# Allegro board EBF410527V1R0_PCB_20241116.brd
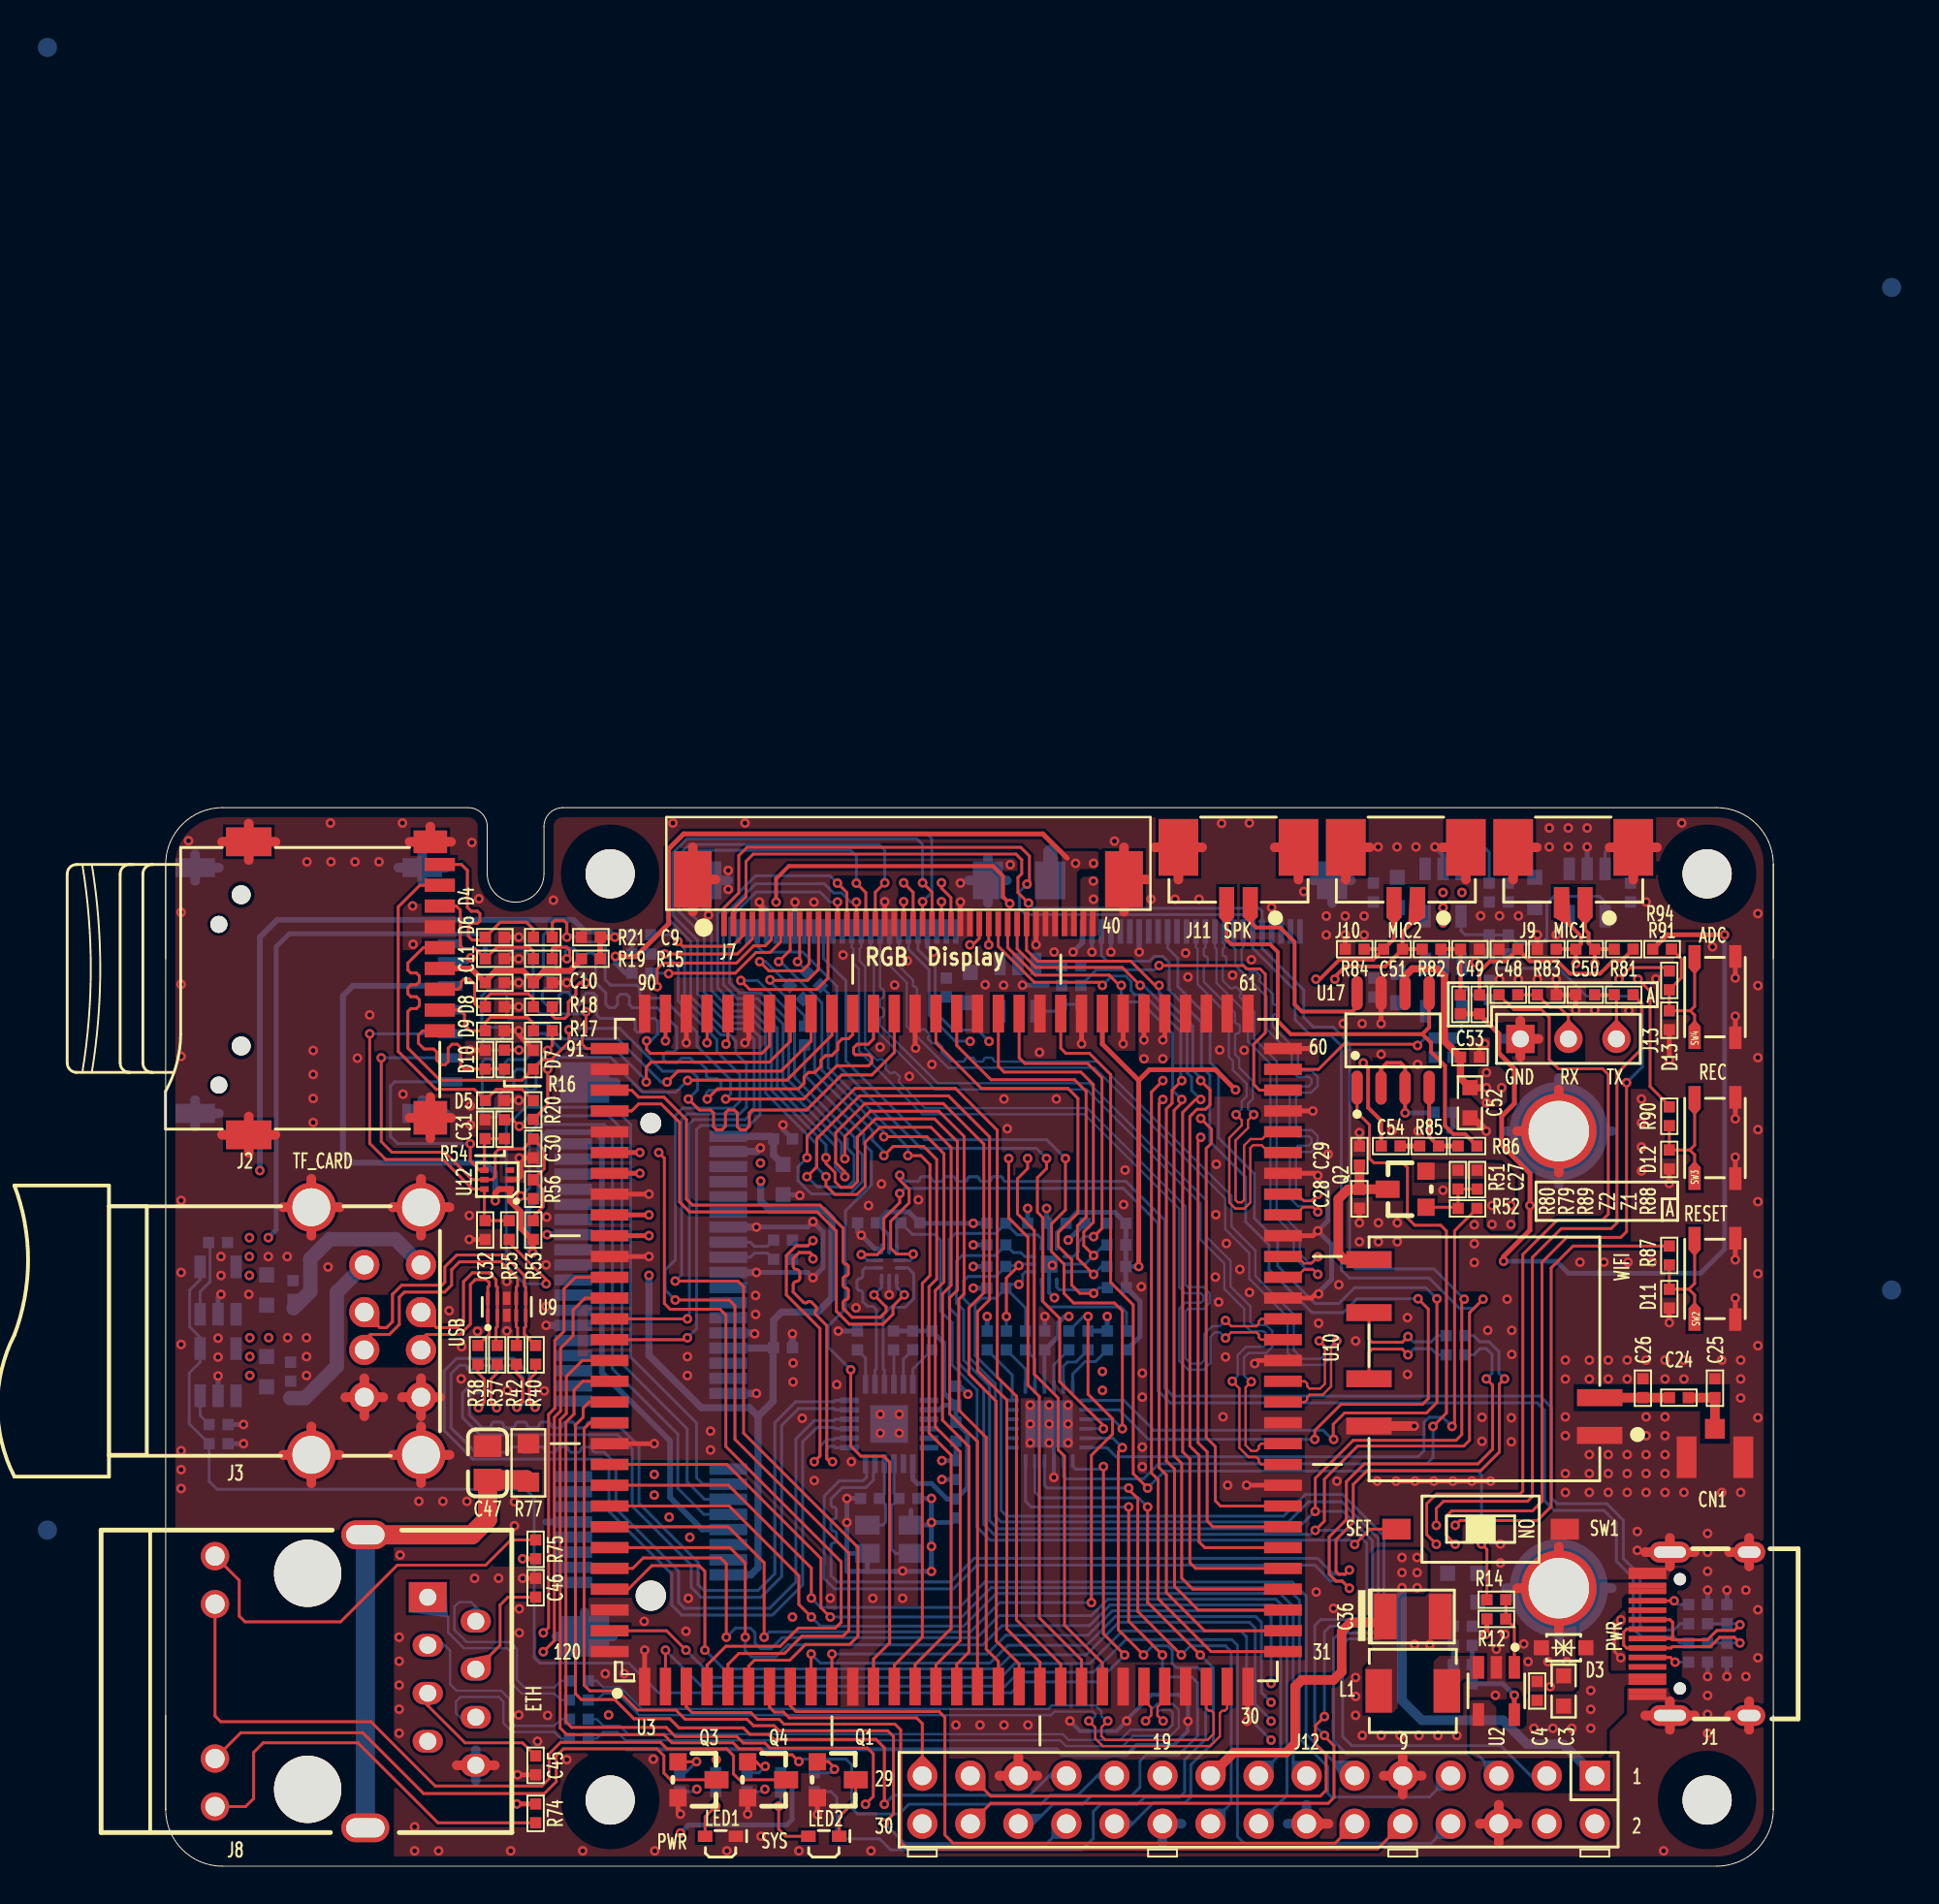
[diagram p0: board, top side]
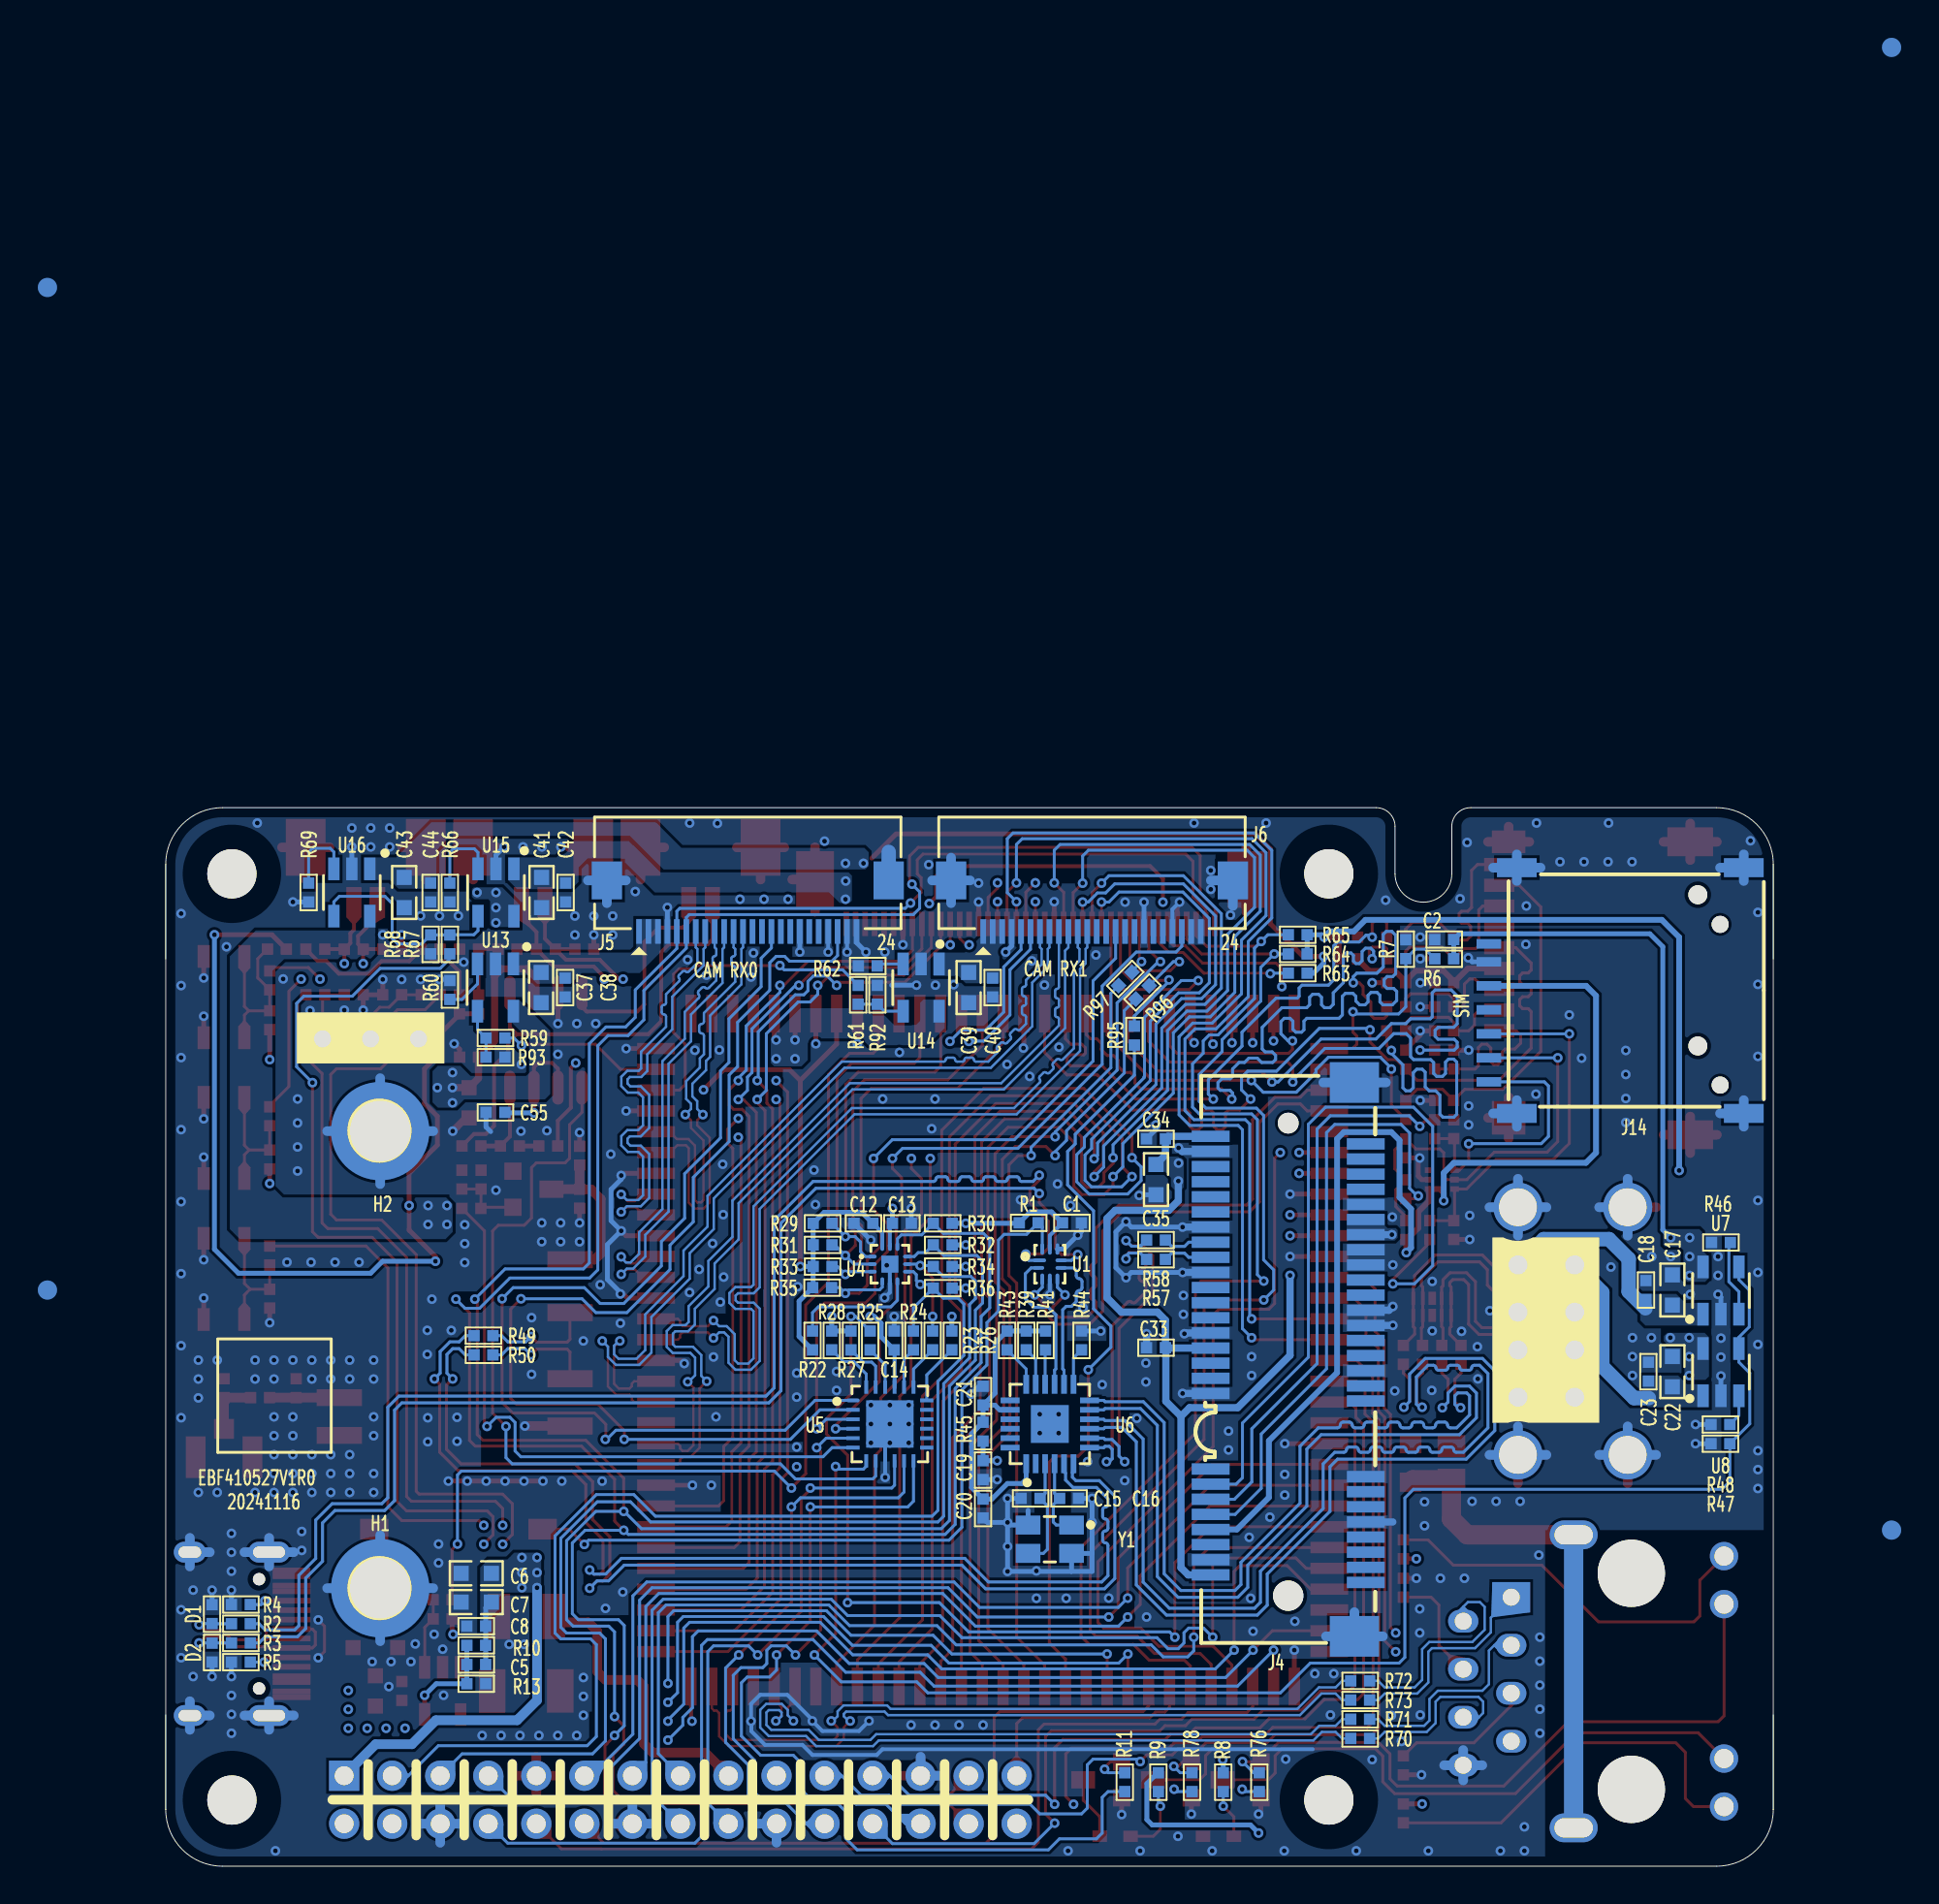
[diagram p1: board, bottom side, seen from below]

Outline 85 x 56 mm; copper layers: TOP, GND02, PWR03, BOTTOM. Coordinates in mm from the lower left corner of the outline.
Outline path: 0,53 0,3 ; 0,53 arc(0.88,55.12) 3,56 16,56 arc(16.71,55.71) 17,55 17,52.5 arc(17.44,51.44) 18.5,51 arc(19.56,51.44) 20,52.5 20,55 arc(20.29,55.71) 21,56 82,56 arc(84.12,55.12) 85,53 ; 0,53 0,48 ; 0,3 0,8 ; 0,3 arc(0.88,0.88) 3,0 82,0 arc(84.12,0.88) 85,3 ; 85,53 85,48 ; 85,53 85,3 ; 85,3 85,8

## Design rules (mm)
net group DBG_DN: nets DBG_DN N21432971
net group DBG_DP: nets DBG_DP N21432968
net group DM1: nets DM1 USB_DM1
net group DM2: nets DM2 USB_DM2
net group DP1: nets DP1 USB_DP1
net group DP2: nets DP2 USB_DP2
net group FEPHY_RXN: nets FEPHY_RXN N23717683
net group FEPHY_RXP: nets FEPHY_RXP N23717680
net group FEPHY_TXN: nets FEPHY_TXN N23717677
net group FEPHY_TXP: nets FEPHY_TXP N23717674
net group I2C3_SCL_LT: nets I2C3_SCL_LT N23825209
net group I2C3_SDA_LT: nets I2C3_SDA_LT N23825224
net group SDMMC_CMD: nets N23503652 SDMMC_CMD
net group SDMMC_D0: nets N23503668 SDMMC_D0
net group SDMMC_D1: nets N23503672 SDMMC_D1
net group SDMMC_D2: nets N23503644 SDMMC_D2
net group SDMMC_D3: nets N23503648 SDMMC_D3
net group SDMMC_DET: nets N23503676 SDMMC_DET
net group USB_4G_DM3: nets N23809847 USB_4G_DM3
net group USB_4G_DP3: nets N23809831 USB_4G_DP3
net group USB_DV: nets USB_RV_DM USB_RV_DP
net group USB_HUB: nets USB_HUB_DM USB_HUB_DP
net group USB_WLAN_DM4: nets N23719058 USB_WLAN_DM4
net group USB_WLAN_DP4: nets N23719056 USB_WLAN_DP4
net group XL9535_INT: nets N23825226 XL9535_INT
net group 50OHM: nets SIM_CLK0 SPI1_CLK_M0 VO_LCDC_CLK
net group PWR: nets HUB_3V3 SIM_VDD VCC3V3_SD VCC_1V8 VCC_WLAN

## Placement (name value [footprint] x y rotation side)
C1  0.1uF  [C0402]  37.08 34.04 180 bottom
C2  0.1uF  [C0402]  17.4 49.02 0 bottom
C3  10uF  [C0603]  73.91 9.27 90 top
C4  0.1uF  [C0402]  72.52 9.27 90 top
C5  22pF  [C0402]  68.58 10.67 0 bottom
C6  10uF  [C0603]  68.58 15.49 0 bottom
C7  10uF  [C0603]  68.58 13.97 0 bottom
C8  0.1uF  [C0402]  68.58 12.7 0 bottom
C9  0.1uF  [C0402]  22.48 49.15 180 top
C10  10uF  [C0402]  19.94 46.74 0 top
C11  0.1uF  [C0402]  17.4 46.74 0 top
C12  1uF  [C0402]  48.11 34.01 0 bottom
C13  1uF  [C0402]  46.08 34.01 180 bottom
C14  10uF  [C0402]  46.48 27.81 90 bottom
C15  NC  [C0402]  39.27 19.46 0 bottom
C16  NC  [C0402]  37.24 19.46 0 bottom
C17  10uF  [C0603]  5.33 30.48 90 bottom
C18  0.1uF  [C0402]  6.73 30.48 90 bottom
C19  0.1uF  [C0402]  41.78 20.95 270 bottom
C20  10uF  [C0402]  41.78 18.92 270 bottom
C21  0.1uF  [C0402]  41.78 24.89 90 bottom
C22  10uF  [C0603]  5.33 26.16 90 bottom
C23  0.1uF  [C0402]  6.6 26.16 90 bottom
C24  10pF  [C0402]  80.01 24.79 180 top
C25  NC  [C0402]  81.92 25.29 90 top
C26  NC  [C0402]  78.11 25.29 90 top
C27  0.1uF  [C0402]  69.34 36.32 270 top
C28  4.7uF  [C0402]  63.12 35.31 270 top
C29  0.1uF  [C0402]  63.12 37.59 90 top
C30  33pF  [C0402]  19.43 37.97 270 top
C31  33pF  [C0402]  16.89 38.99 90 top
C32  33pF  [C0402]  16.89 33.66 270 top
C33  0.1uF  [C0402]  32.64 27.43 0 bottom
C34  0.1uF  [C0402]  32.64 38.48 0 bottom
C35  10uF  [C0603]  32.64 36.32 270 bottom
C36  220uF  [CASE-B_3528]  65.94 13.21 0 top
C37  10uF  [C0603]  65.15 46.48 270 bottom
C38  0.1uF  [C0402]  63.88 46.48 270 bottom
C39  10uF  [C0603]  42.55 46.48 270 bottom
C40  0.1uF  [C0402]  41.27 46.48 270 bottom
C41  10uF  [C0603]  65.13 51.51 270 bottom
C42  0.1uF  [C0402]  63.86 51.51 270 bottom
C43  10uF  [C0603]  72.39 51.51 270 bottom
C44  0.1uF  [C0402]  70.99 51.51 270 bottom
C45  22nF  [C0402]  19.56 5.33 270 top
C46  22nF  [C0402]  19.56 14.73 90 top
C47  1nF  [C0805]  17.02 21.34 90 top
C48  NC  [C0402]  70.99 48.51 180 top
C49  NC  [C0402]  68.96 48.51 0 top
C50  NC  [C0402]  75.06 48.51 180 top
C51  NC  [C0402]  64.9 48.51 180 top
C52  10uF  [C0603]  68.96 40.39 270 top
C53  0.1uF  [C0402]  68.96 42.8 0 top
C54  0.22uF  [C0402]  64.77 38.1 0 top
C55  1uF  [C0402]  67.56 39.88 0 bottom
CN1  WiFi-Ant  [UFL-3]  81.92 21.64 180 top
D1  KLXES15AAA1  [ES0402]  82.55 13.34 270 bottom
D2  KLXES15AAA1  [ES0402]  82.55 11.3 90 bottom
D3  PESD5V0S1BA-N  [SOD323_CA]  73.91 11.56 180 top
D4  KLXES15AAA1  [ES0402]  17.4 49.15 0 top
D5  KLXES15AAA1  [ES0402]  17.4 40.51 0 top
D6  KLXES15AAA1  [ES0402]  17.4 48.01 0 top
D7  KLXES15AAA1  [ES0402]  19.43 42.67 90 top
D8  KLXES15AAA1  [ES0402]  17.4 45.47 0 top
D9  KLXES15AAA1  [ES0402]  17.4 44.2 0 top
D10  KLXES15AAA1  [ES0402]  16.89 42.67 90 top
D11  KLXES15AAA1  [ES0402]  79.5 30.02 90 top
D12  KLXES15AAA1  [ES0402]  79.5 37.39 90 top
D13  KLXES15AAA1  [ES0402]  79.5 44.75 90 top
H1  M2X3mm  [T3R2-5R2_TOPSMT]  73.66 14.71 180 bottom
H2  M2X3mm  [T3R2-5R2_TOPSMT]  73.66 38.89 180 bottom
J1  TYPE-C  [TYPE-C-31-M-12]  78.62 12.29 90 top
J2  TF_Card  [TFCARD]  3.99 47.39 270 top
J3  -  [USB-A-D]  7 28.31 90 top
J4  MINI-PCIE  [PCIE_52P]  25.65 26.81 90 bottom
J5  FPC_0P5_24P_D  [FPC_24P_0P5]  54.22 50.8 180 bottom
J6  FPC_0P5_24P_D  [FPC_24P_0P5]  36.02 50.8 180 bottom
J7  FPC_0R5_40P_D  [FPC-40P-0P5]  39.27 49.85 0 top
J8  HR911105A  [RJ45]  9.28 10.29 90 top
J9  -  [YTC-A1251-02AB]  74.42 51 0 top
J10  -  [YTC-A1251-02AB]  65.57 51 0 top
J11  -  [YTC-A1251-02AB]  56.72 51 0 top
J12  -  [HDR2X15-2R54-TM-VM]  57.78 3.52 180 top
J13  1X3PIN-M  [DIP_3P_2P54]  74.17 43.77 0 top
J14  SIM-7-1  [NANO_SIM]  8.3 46.32 90 bottom
L1  3.3uH  [L4520]  65.94 9.27 180 top
LED1  HS-0602-UR  [LED_HS_0602_UR]  29.34 1.58 180 top
LED2  HS-0602-UG  [LED_HS_0602_UR]  34.8 1.58 180 top
NOREF  -  []  -2 0 90 top
NOREF#2  -  []  79.25 24.89 0 top
NOREF#3  -  []  -10 1.52 0 top
NOREF#4  -  [unnamed#2]  -6.25 17.78 0 bottom
NOREF#5  -  [unnamed#2]  91.25 30.48 0 bottom
NOREF#6  -  [unnamed#2]  91.25 83.52 0 bottom
NOREF#7  -  [unnamed#2]  -6.25 96.22 0 bottom
Q1  SS8050  [SOT23]  35.45 4.57 270 top
Q2  SI2333  [SOT23]  65.65 35.81 90 top
Q3  SS8050  [SOT23]  28.08 4.57 270 top
Q4  SS8050  [SOT23]  31.76 4.57 270 top
R1  4.7K  [R0402]  39.37 34.04 180 bottom
R2  2.2R  [R0402]  81.03 12.83 180 bottom
R3  2.2R  [R0402]  81.03 11.81 180 bottom
R4  5.1K  [R0402]  81.03 13.84 0 bottom
R5  5.1K  [R0402]  81.03 10.79 0 bottom
R6  12K  [R0402]  17.4 48.01 0 bottom
R7  22K  [R0402]  19.43 48.51 90 bottom
R8  4.7K  [R0402]  29.08 4.45 270 bottom
R9  2.2K  [R0402]  32.51 4.45 270 bottom
R10  100K  [R0402]  68.58 11.68 0 bottom
R11  1K  [R0402]  34.29 4.45 90 bottom
R12  0R  [R0402]  70.36 13.08 0 top
R13  22K  [R0402]  68.58 9.65 180 bottom
R14  NC  [R0402]  70.36 14.1 0 top
R15  0R  [R0402]  22.48 48.01 180 top
R16  22R  [R0402]  17.91 42.67 270 top
R17  22R  [R0402]  19.94 44.2 180 top
R18  22R  [R0402]  19.94 45.47 180 top
R19  22R  [R0402]  19.94 48.01 180 top
R20  22R  [R0402]  19.43 40.01 90 top
R21  1K  [R0402]  19.94 49.15 180 top
R22  10K  [R0402]  50.8 27.81 90 bottom
R23  22R  [R0402]  44.45 27.81 270 bottom
R24  22R  [R0402]  45.47 27.81 270 bottom
R25  22R  [R0402]  47.75 27.81 270 bottom
R26  10K  [R0402]  43.43 27.81 270 bottom
R27  NC  [R0402]  48.77 27.81 270 bottom
R28  NC  [R0402]  49.78 27.81 270 bottom
R29  4.7K  [R0402]  50.27 34.01 180 bottom
R30  4.7K  [R0402]  43.92 34.01 0 bottom
R31  4.7K  [R0402]  50.27 32.87 180 bottom
R32  4.7K  [R0402]  43.92 32.87 0 bottom
R33  4.7K  [R0402]  50.27 31.72 180 bottom
R34  4.7K  [R0402]  43.92 31.72 0 bottom
R35  4.7K  [R0402]  50.29 30.61 180 bottom
R36  4.7K  [R0402]  43.92 30.58 0 bottom
R37  2.2R  [R0402]  17.53 27.05 270 top
R38  2.2R  [R0402]  16.51 27.05 270 top
R39  NC  [R0402]  39.5 27.81 270 bottom
R40  2.2R  [R0402]  19.56 27.05 270 top
R41  100K  [R0402]  38.48 27.81 270 bottom
R42  2.2R  [R0402]  18.54 27.05 270 top
R43  100K  [R0402]  40.51 27.81 270 bottom
R44  NC  [R0402]  36.58 27.81 90 bottom
R45  0R  [R0402]  41.78 22.99 90 bottom
R46  3.4K  [R0402]  2.77 32.99 0 bottom
R47  10K  [R0402]  2.79 22.35 0 bottom
R48  3.4K  [R0402]  2.79 23.37 0 bottom
R49  2.2R  [R0402]  68.2 28.07 180 bottom
R50  2.2R  [R0402]  68.2 27.05 180 bottom
R51  10K  [R0402]  68.33 36.32 270 top
R52  1K  [R0402]  68.83 34.8 180 top
R53  15K  [R0402]  19.43 33.66 90 top
R54  0R  [R0402]  17.91 38.99 270 top
R55  0R  [R0402]  18.16 33.66 90 top
R56  0R  [R0402]  19.43 35.81 90 top
R57  2.2R  [R0402]  32.64 32.11 0 bottom
R58  2.2R  [R0402]  32.64 33.12 0 bottom
R59  1K  [R0402]  67.56 43.81 0 bottom
R60  6.8K  [R0402]  69.98 46.35 90 bottom
R61  1K  [R0402]  48.39 46.1 270 bottom
R62  6.8K  [R0402]  47.88 47.62 0 bottom
R63  10K  [R0402]  25.15 47.24 0 bottom
R64  10K  [R0402]  25.15 48.26 0 bottom
R65  10K  [R0402]  25.15 49.28 0 bottom
R66  6.8K  [R0402]  69.98 51.51 270 bottom
R67  1K  [R0402]  69.98 48.77 90 bottom
R68  10K  [R0402]  70.99 48.77 270 bottom
R69  6.8K  [R0402]  77.44 51.51 270 bottom
R70  0R  [R0402]  21.84 6.76 180 bottom
R71  0R  [R0402]  21.84 7.77 180 bottom
R72  0R  [R0402]  21.84 9.8 180 bottom
R73  0R  [R0402]  21.84 8.79 180 bottom
R74  1K  [R0402]  19.56 2.79 270 top
R75  1K  [R0402]  19.56 16.76 90 top
R76  1K  [R0402]  27.18 4.45 90 bottom
R77  1M  [R0805]  19.18 21.34 90 top
R78  1K  [R0402]  30.73 4.45 90 bottom
R79  NC  [R0402]  69.47 45.59 90 top
R80  NC  [R0402]  68.45 45.59 90 top
R81  NC  [R0402]  77.09 48.51 0 top
R82  NC  [R0402]  66.93 48.51 0 top
R83  NC  [R0402]  73.03 48.51 180 top
R84  NC  [R0402]  62.87 48.51 180 top
R85  20K  [R0402]  66.8 38.1 0 top
R86  100K  [R0402]  68.83 38.1 0 top
R87  100R  [R0402]  79.5 32.31 270 top
R88  510R  [R0402]  77.09 46.1 0 top
R89  510R  [R0402]  70.99 46.1 180 top
R90  100R  [R0402]  79.5 39.67 270 top
R91  100R  [R0402]  79.5 46.86 270 top
R92  10K  [R0402]  47.37 46.1 90 bottom
R93  10K  [R0402]  67.56 42.8 180 bottom
R94  10K  [R0402]  79.12 48.51 180 top
R95  40.2R  [R0402]  33.78 43.94 90 bottom
R96  40.2R  [R0402]  33.35 46.23 135 bottom
R97  40.2R  [R0402]  34.26 46.94 135 bottom
SS1  NPTH_M2.5  [NPTH_M2R5]  23.5 3.5 0 top
SS2  NPTH_M2.5  [NPTH_M2R5]  81.5 3.5 0 top
SS3  NPTH_M2.5  [NPTH_M2R5]  81.5 52.5 0 top
SS4  NPTH_M2.5  [NPTH_M2R5]  23.5 52.5 0 top
SW1  DSIC01LS-P  [SW2-6R20X3R50-SM]  69.52 17.83 0 top
SW2  SW_PB_ESW  [SW4-4R20X3R25-SM]  81.92 31.07 270 top
SW3  SW_PB_ESW  [SW4-4R20X3R25-SM]  81.92 38.52 270 top
SW4  SW_PB_ESW  [SW4-4R20X3R25-SM]  81.92 45.98 270 top
U1  TS3USB30ERSWR  [UQFN_10]  38.25 31.85 180 bottom
U2  RY3430  [SOT23-5]  70.36 9.27 180 top
U3  -  [RV1106-35X35-HOLE-B-120P]  41.27 27.3 0 top
U4  RS0104YTQE12  [QFN12L-0R4-2X2EP1R20X1R00]  46.71 31.85 180 bottom
U5  XL9535QF24  [QFN24-4X4EP2R70X2R70]  46.71 23.39 180 bottom
U6  CH334F  [QFN24]  38.25 23.39 90 bottom
U7  LPW5209AB5F  [SOT23-5]  2.77 30.45 180 bottom
U8  LPW5209AB5F  [SOT23-5]  2.77 26.14 180 bottom
U9  RCLAMP0524P  [USON_10]  18.03 29.59 0 top
U10  TL8800DLUA  [SMD6-12R9X12R2]  69.72 26.84 90 top
U12  NUP5120X6T1G  [SOT563]  17.53 36.32 90 top
U13  LPW5209AB5F  [SOT23-5]  67.56 46.48 0 bottom
U14  LPW5209AB5F  [SOT23-5]  45.06 46.48 0 bottom
U15  LPW5209AB5F  [SOT23-5]  67.54 51.51 0 bottom
U16  LPW5209AB5F  [SOT23-5]  75.16 51.51 0 bottom
U17  8002A  [SOP8]  64.9 43.69 0 top
Y1  12MHz  [3225]  38.25 17.3 0 bottom
Z1  KLXES15AAA1  [ES0402]  75.06 46.1 180 top
Z2  KLXES15AAA1  [ES0402]  73.03 46.1 0 top

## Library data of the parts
C1-C35 C37-C55 = CAP_NP
C36 = CAP
CN1 = WIFI_ANT
D1-D13 Z1 Z2 = DIODE BI-DIR TRIG
H1 H2 SS1-SS4 = SPACER
J1 = TYPE-C-31-M-12
J2 = TF_Card
J3 = USB-A-D
J4 = MINI-PCIE
J5 J6 = FPC-24P
J7 = FPC-40P
J8 = RJ45_HR961160C
J9-J11 = 1X2PIN_SH
J12 = 2X15PIN
J13 = 1X3PIN
J14 = SIM-7-1
L1 = IND
LED1 LED2 = LED
Q1 Q3 Q4 = NPN
Q2 = MOSFET_P
R1 R4-R15 R22 R26-R36 R39 R41 R43-R48 R51-R56 R59-R69 R74-R97 = RES
R2 R3 R37 R38 R40 R42 R49 R50 R57 R58 = RES: signal model: RES_R0402_DISCRETE_2.2R_2.2R
R16-R20 R23-R25 = RES: signal model: RES_R0402_DISCRETE_22R_22R
R21 = RES: signal model: RES_R0402_DISCRETE_1K_1K
R70-R73 = RES: signal model: RES_R0402_DISCRETE_0R_0R
SW1 = SW01
SW2-SW4 = SW_PB_ESW
U1 = TS3USB30ERSWR
U2 = MT3520B
U3 = RV1106G_CORE_120P
U4 = RS0104YTQE12
U5 = XL9535QF24
U6 = CH334F
U7 U8 U13-U16 = LPW5209AB5F
U9 = RCLAMP0524P
U10 = TL8800DLUA
U12 = NUP5120-D
U17 = 8002A
Y1 = CRYSTAL_4P

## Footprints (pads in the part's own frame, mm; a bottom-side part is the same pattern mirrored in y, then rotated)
3225
  rect 1.3x1 smd: 1(-1.15,-0.75) 2(1.15,-0.75) 3(1.15,0.75) 4(-1.15,0.75)
C0402
  rect 0.599x0.599 smd: 1(-0.5,0) 2(0.5,0)
C0603
  rect 0.8x0.8 smd: 1(-0.8,0) 2(0.8,0)
C0805
  rect 1.16x1.47 smd: 1(-0.89,0) 2(0.89,0)
CASE-B_3528
  rect 1.2x2.4 smd: 1(-1.45,0) 2(1.45,0)
DIP_3P_2P54
  rect 1.5x1.5 hole 0.9: 1(-2.54,0)
  round 1.5 hole 0.9: 2(0,0) 3(2.54,0)
ES0402
  rect 0.599x0.599 smd: 1(-0.5,0) 2(0.5,0)
FPC-40P-0P5
  rect 0.3x1.3 smd: 1(-9.75,0) 2(-9.25,0) 3(-8.75,0) 4(-8.25,0) 5(-7.75,0) 6(-7.25,0) 7(-6.75,0) 8(-6.25,0) 9(-5.75,0) 10(-5.25,0) 11(-4.75,0) 12(-4.25,0) 13(-3.75,0) 14(-3.25,0) 15(-2.75,0) 16(-2.25,0) 17(-1.75,0) 18(-1.25,0) 19(-0.75,0) 20(-0.25,0) 21(0.25,0) 22(0.75,0) 23(1.25,0) 24(1.75,0) 25(2.25,0) 26(2.75,0) 27(3.25,0) 28(3.75,0) 29(4.25,0) 30(4.75,0) 31(5.25,0) 32(5.75,0) 33(6.25,0) 34(6.75,0) 35(7.25,0) 36(7.75,0) 37(8.25,0) 38(8.75,0) 39(9.25,0) 40(9.75,0)
  rect 2x3 smd: 41(11.4,2.35) 42(-11.4,2.35)
FPC_24P_0P5
  rect 0.3x1.3 smd: 1(-5.75,-1.351) 2(-5.25,-1.351) 3(-4.75,-1.351) 4(-4.25,-1.351) 5(-3.75,-1.351) 6(-3.25,-1.351) 7(-2.75,-1.351) 8(-2.25,-1.351) 9(-1.75,-1.351) 10(-1.25,-1.351) 11(-0.75,-1.351) 12(-0.25,-1.351) 13(0.25,-1.351) 14(0.75,-1.351) 15(1.25,-1.351) 16(1.75,-1.351) 17(2.25,-1.351) 18(2.75,-1.351) 19(3.25,-1.351) 20(3.75,-1.351) 21(4.25,-1.351) 22(4.75,-1.351) 23(5.25,-1.351) 24(5.75,-1.351)
  rect 1.6x2 smd: 25(7.45,1.351) 26(-7.45,1.351)
HDR2X15-2R54-TM-VM
  rect 1.6x1.6 hole 1: 1(-17.78,-1.27)
  round 1.6 hole 1: 2(-17.78,1.27) 3(-15.24,-1.27) 4(-15.24,1.27) 5(-12.7,-1.27) 6(-12.7,1.27) 7(-10.16,-1.27) 8(-10.16,1.27) 9(-7.62,-1.27) 10(-7.62,1.27) 11(-5.08,-1.27) 12(-5.08,1.27) 13(-2.54,-1.27) 14(-2.54,1.27) 15(0,-1.27) 16(0,1.27) 17(2.54,-1.27) 18(2.54,1.27) 19(5.08,-1.27) 20(5.08,1.27) 21(7.62,-1.27) 22(7.62,1.27) 23(10.16,-1.27) 24(10.16,1.27) 25(12.7,-1.27) 26(12.7,1.27) 27(15.24,-1.27) 28(15.24,1.27) 29(17.78,-1.27) 30(17.78,1.27)
L4520
  rect 1.4x2.3 smd: 1(-1.8,0) 2(1.8,0)
LED_HS_0602_UR
  rect 0.77x0.599 smd: 1(-0.815,0) 2(0.815,0)
NANO_SIM
  round 0.9 hole 0.9 unplated: (-5,-5.49) (3.5,-5.49)
  rect 0.5x1.3 smd: 1(0.25,6.74) 2(-2.29,6.74) 3(-4.83,6.74) 4(2.47,6.74) 5(1.52,6.74) 6(-1.02,6.74) 7(-3.56,6.74)
  rect 1x2.1 smd: 8(-6.5,5.26) 9(6.5,5.26) 10(-6.5,-6.74) 11(6.5,-6.74)
NPTH_M2R5
  round 2.6 hole 2.6 unplated: (0,0)
PCIE_52P
  round 1.6 hole 1.6 unplated: (-12.5,0)
  round 1.1 hole 1.1 unplated: (12.5,0)
  rect 0.6x2 smd: 1(-11.8,-4.1) 2(-11.4,4.1) 3(-11,-4.1) 4(-10.6,4.1) 5(-10.2,-4.1) 6(-9.8,4.1) 7(-9.4,-4.1) 8(-9,4.1) 9(-8.6,-4.1) 10(-8.2,4.1) 11(-7.8,-4.1) 12(-7.4,4.1) 13(-7,-4.1) 14(-6.6,4.1) 15(-6.2,-4.1) 16(-5.8,4.1) 17(-2.2,-4.1) 18(-1.8,4.1) 19(-1.4,-4.1) 20(-1,4.1) 21(-0.6,-4.1) 22(-0.2,4.1) 23(0.2,-4.1) 24(0.6,4.1) 25(1,-4.1) 26(1.4,4.1) 27(1.8,-4.1) 28(2.2,4.1) 29(2.6,-4.1) 30(3,4.1) 31(3.4,-4.1) 32(3.8,4.1) 33(4.2,-4.1) 34(4.6,4.1) 35(5,-4.1) 36(5.4,4.1) 37(5.8,-4.1) 38(6.2,4.1) 39(6.6,-4.1) 40(7,4.1) 41(7.4,-4.1) 42(7.8,4.1) 43(8.2,-4.1) 44(8.6,4.1) 45(9,-4.1) 46(9.4,4.1) 47(9.8,-4.1) 48(10.2,4.1) 49(10.6,-4.1) 50(11,4.1) 51(11.4,-4.1) 52(11.8,4.1)
  rect 2.15x2.6 smd: 53(14.65,-3.5) 54(-14.65,-3.5)
QFN12L-0R4-2X2EP1R20X1R00
  oval 0.45x0.2 smd: 1(-0.925,0.4) 2(-0.925,0) 3(-0.925,-0.4) 7(0.925,-0.4) 8(0.925,0) 9(0.925,0.4)
  oval 0.2x0.45 smd: 4(-0.4,-0.925) 5(0,-0.925) 6(0.4,-0.925) 10(0.4,0.925) 11(0,0.925) 12(-0.4,0.925)
  rect 0.9x0.9 smd: 13(0,0)
QFN24
  rect 1x0.3 smd: 1(-2.1,1.25) 2(-2.1,0.75) 3(-2.1,0.25) 4(-2.1,-0.25) 5(-2.1,-0.75) 6(-2.1,-1.25) 13(2.1,-1.25) 14(2.1,-0.75) 15(2.1,-0.25) 16(2.1,0.25) 17(2.1,0.75) 18(2.1,1.25)
  rect 0.3x1 smd: 7(-1.25,-2.1) 8(-0.75,-2.1) 9(-0.25,-2.1) 10(0.25,-2.1) 11(0.75,-2.1) 12(1.25,-2.1) 19(1.25,2.1) 20(0.75,2.1) 21(0.25,2.1) 22(-0.25,2.1) 23(-0.75,2.1) 24(-1.25,2.1)
  rect 2x2 smd: 25(0,0)
QFN24-4X4EP2R70X2R70
  oval 0.7x0.2 smd: 1(-1.95,1.25)
  rect 0.7x0.2 smd: 2(-1.95,0.75) 3(-1.95,0.25) 4(-1.95,-0.25) 5(-1.95,-0.75) 6(-1.95,-1.25) 13(1.95,-1.25) 14(1.95,-0.75) 15(1.95,-0.25) 16(1.95,0.25) 17(1.95,0.75) 18(1.95,1.25)
  rect 0.2x0.7 smd: 7(-1.25,-1.95) 8(-0.75,-1.95) 9(-0.25,-1.95) 10(0.25,-1.95) 11(0.75,-1.95) 12(1.25,-1.95) 19(1.25,1.95) 20(0.75,1.95) 21(0.25,1.95) 22(-0.25,1.95) 23(-0.75,1.95) 24(-1.25,1.95)
  rect 2.5x2.5 smd: 25(0,0)
R0402
  rect 0.599x0.599 smd: 1(-0.5,0) 2(0.5,0)
R0805
  rect 1.016x1.143 smd: 1(-1.016,0) 2(1.016,0)
RJ45
  round 3.556 hole 3.556 unplated: (-6.223,1.778) (5.207,1.778)
  rect 1.6x2 hole 0.9: 1(3.942,-4.572)
  oval 1.2x1.6 hole 0.9: 2(2.672,-7.112) 3(1.402,-4.572) 4(0.132,-7.112) 5(-1.138,-4.572) 6(-2.408,-7.112) 7(-3.678,-4.572) 8(-4.948,-7.112)
  round 1.5 hole 1.02: 9(6.117,6.678) 10(3.577,6.678) 11(-4.593,6.678) 12(-7.133,6.678)
  oval 1.524x2.54 hole 1.016x2.032: 13(7.242,-1.272) 14(-8.258,-1.272)
RV1106-35X35-HOLE-B-120P
  rect 0.6x2 smd: 1(-15.95,-17.8) 2(-14.85,-17.8) 3(-13.75,-17.8) 4(-12.65,-17.8) 5(-11.55,-17.8) 6(-10.45,-17.8) 7(-9.35,-17.8) 8(-8.25,-17.8) 9(-7.15,-17.8) 10(-6.05,-17.8) 11(-4.95,-17.8) 12(-3.85,-17.8) 13(-2.75,-17.8) 14(-1.65,-17.8) 15(-0.55,-17.8) 16(0.55,-17.8) 17(1.65,-17.8) 18(2.75,-17.8) 19(3.85,-17.8) 20(4.95,-17.8) 21(6.05,-17.8) 22(7.15,-17.8) 23(8.25,-17.8) 24(9.35,-17.8) 25(10.45,-17.8) 26(11.55,-17.8) 27(12.65,-17.8) 28(13.75,-17.8) 29(14.85,-17.8) 30(15.95,-17.8) 61(15.95,17.8) 62(14.85,17.8) 63(13.75,17.8) 64(12.65,17.8) 65(11.55,17.8) 66(10.45,17.8) 67(9.35,17.8) 68(8.25,17.8) 69(7.15,17.8) 70(6.05,17.8) 71(4.95,17.8) 72(3.85,17.8) 73(2.75,17.8) 74(1.65,17.8) 75(0.55,17.8) 76(-0.55,17.8) 77(-1.65,17.8) 78(-2.75,17.8) 79(-3.85,17.8) 80(-4.95,17.8) 81(-6.05,17.8) 82(-7.15,17.8) 83(-8.25,17.8) 84(-9.35,17.8) 85(-10.45,17.8) 86(-11.55,17.8) 87(-12.65,17.8) 88(-13.75,17.8) 89(-14.85,17.8) 90(-15.95,17.8)
  rect 2x0.6 smd: 31(17.8,-15.95) 32(17.8,-14.85) 33(17.8,-13.75) 34(17.8,-12.65) 35(17.8,-11.55) 36(17.8,-10.45) 37(17.8,-9.35) 38(17.8,-8.25) 39(17.8,-7.15) 40(17.8,-6.05) 41(17.8,-4.95) 42(17.8,-3.85) 43(17.8,-2.75) 44(17.8,-1.65) 45(17.8,-0.55) 46(17.8,0.55) 47(17.8,1.65) 48(17.8,2.75) 49(17.8,3.85) 50(17.8,4.95) 51(17.8,6.05) 52(17.8,7.15) 53(17.8,8.25) 54(17.8,9.35) 55(17.8,10.45) 56(17.8,11.55) 57(17.8,12.65) 58(17.8,13.75) 59(17.8,14.85) 60(17.8,15.95) 91(-17.8,15.95) 92(-17.8,14.85) 93(-17.8,13.75) 94(-17.8,12.65) 95(-17.8,11.55) 96(-17.8,10.45) 97(-17.8,9.35) 98(-17.8,8.25) 99(-17.8,7.15) 100(-17.8,6.05) 101(-17.8,4.95) 102(-17.8,3.85) 103(-17.8,2.75) 104(-17.8,1.65) 105(-17.8,0.55) 106(-17.8,-0.55) 107(-17.8,-1.65) 108(-17.8,-2.75) 109(-17.8,-3.85) 110(-17.8,-4.95) 111(-17.8,-6.05) 112(-17.8,-7.15) 113(-17.8,-8.25) 114(-17.8,-9.35) 115(-17.8,-10.45) 116(-17.8,-11.55) 117(-17.8,-12.65) 118(-17.8,-13.75) 119(-17.8,-14.85) 120(-17.8,-15.95)
SMD6-12R9X12R2
  rect 0.9x2.4 smd: 1(-4.05,-6.1) 2(-2.05,-6.1) 3(-3.55,6.1) 4(-1.05,6.1) 5(2.45,6.1) 6(5.25,6.1)
SOD323_CA
  rect 0.8x0.8 smd: 1(-1.175,0) 2(1.175,0)
SOP8
  oval 0.6x1.8 smd: 1(-1.905,-2.5) 2(-0.635,-2.5) 3(0.635,-2.5) 4(1.905,-2.5) 5(1.905,2.5) 6(0.635,2.5) 7(-0.635,2.5) 8(-1.905,2.5)
SOT23
  rect 0.914x0.914 smd: 1(-0.953,-0.991) 2(0.953,-0.991)
  rect 0.914x1.27 smd: 3(0,1.041)
SOT23-5
  rect 0.599x1.199 smd: 1(-0.95,-1.25) 2(0,-1.25) 3(0.95,-1.25) 4(0.95,1.25) 5(-0.95,1.25)
SOT563
  rect 0.3x0.45 smd: 1(-0.5,-0.675) 2(0,-0.675) 3(0.5,-0.675) 4(0.5,0.675) 5(0,0.675) 6(-0.5,0.675)
SW2-6R20X3R50-SM
  rect 1.5x1.1 smd: 1(-4.45,0) 2(4.45,0)
SW4-4R20X3R25-SM
  rect 1.2x0.65 smd: 1(-2.15,1.075) 2(2.15,1.075) 3(2.15,-1.075) 4(-2.15,-1.075)
T3R2-5R2_TOPSMT
  round 4 hole 3.2: 1(0,0)
TFCARD
  round 1 hole 1 unplated: (-4,0) (4,0)
  rect 0.7x1.6 smd: 1(3.2,10.5) 2(2.1,10.5) 3(1,10.5) 4(-0.1,10.5) 5(-1.2,10.5) 6(-2.3,10.5) 7(-3.4,10.5) 8(-4.5,10.5) 9(-5.6,10.5)
  rect 1.2x1.778 smd: 10(-6.8,10)
  rect 1.524x2.413 smd: 11(-6.8,0.4) 12(8.7,0.4)
  rect 1.778x1.778 smd: 13(7.8,10)
TYPE-C-31-M-12
  round 0.65 hole 0.65 unplated: (-2.891,-1.44) (2.891,-1.44)
  rect 0.3x2 smd: A1(-3.35,0.279) A4(-2.55,0.279) A5(-1.25,0.279) A6(-0.249,0.279) A7(0.249,0.279) A8(1.25,0.279) A9(2.55,0.279) A12(3.35,0.279) B1(3.051,0.279) B4(2.25,0.279) B5(1.75,0.279) B6(0.749,0.279) B7(-0.749,0.279) B8(-1.75,0.279) B9(-2.25,0.279) B12(-3.051,0.279)
  oval 1.1x1.699 hole 0.599x1.199: C1(-4.321,-5.1) C2(4.321,-5.1)
  oval 1.1x2.2 hole 0.599x1.699: C3(-4.321,-0.909) C4(4.321,-0.909)
UFL-3
  rect 1.05x1.05 smd: 1(0,-1.5)
  rect 1.05x2.2 smd: 2(-1.5,0) 3(1.5,0)
unnamed#2
  round 1.016 smd: (0,0)
UQFN_10
  oval 0.7x0.2 smd: 1(-0.55,0.2)
  oval 0.6x0.2 smd: 2(-0.6,-0.2) 6(0.6,-0.2) 7(0.6,0.2)
  oval 0.2x0.6 smd: 3(-0.4,-0.8) 4(0,-0.8) 5(0.4,-0.8) 8(0.4,0.8) 9(0,0.8) 10(-0.4,0.8)
USB-A-D
  round 1.6 hole 1: 1(3.5,-6.5) 2(1,-6.5) 3(-1,-6.5) 4(-3.5,-6.5) 7(3.5,-3.5) 8(1,-3.5) 9(-1,-3.5) 10(-3.5,-3.5)
  round 2.6 hole 2: 5(-6.55,-6.5) 6(6.55,-6.5) 11(-6.55,-0.7) 12(6.55,-0.7)
USON_10
  rect 0.2x0.7 smd: 1(-1,-0.45) 2(-0.5,-0.45) 4(0.5,-0.45) 5(1,-0.45) 6(1,0.45) 7(0.5,0.45) 9(-0.5,0.45) 10(-1,0.45)
  rect 0.4x0.7 smd: 3(0,-0.45) 8(0,0.45)
YTC-A1251-02AB
  rect 0.8x1.6 smd: 1(0.625,0) 2(-0.625,0)
  rect 2.1x3 smd: 3(3.175,2.9) 4(-3.175,2.9)

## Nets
GND: C1.2 C2.2 C3.2 C4.2 C6.2 C7.2 C8.2 C9.2 C10.2 C11.2 C12.2 C13.2 C14.2 C15.2 C16.1 C17.2 C18.2 C19.2 C20.2 C21.2 C22.2 C23.2 C25.2 C26.2 C28.2 C29.2 C30.2 C31.2 C32.2 C33.2 C34.2 C35.2 C36.2 C37.2 C38.2 C39.2 C40.2 C41.2 C42.2 C43.2 C44.2 C45.2 C46.2 C47.2 C48.2 C49.2 C52.2 C53.2 C55.2 CN1.2 CN1.3 D1.1 D2.1 D3.2 D4.2 D5.2 D6.2 D7.2 D8.2 D9.2 D10.2 D11.1 D12.1 D13.1 H1.1(NC_1) H2.1(NC_1) J1.A1(GND1) J1.A12(GND2) J1.B1(GND4) J1.B12(GND3) J1.C1(SH1) J1.C2(SH2) J1.C3(SH3) J1.C4(SH4) J2.6(VSS) J2.10(GND10) J2.11(GND11) J2.12(GND12) J2.13(GND13) J3.4(GND) J3.5(SH1) J3.6(SH2) J3.10(GND) J3.11(SH1) J3.12(SH2) J4.4(GND9) J4.9(GND1) J4.15(GND2) J4.18(GND10) J4.21(GND3) J4.26(GND11) J4.27(GND4) J4.29(GND5) J4.34(GND12) J4.35(GND6) J4.37(GND7) J4.40(GND13) J4.43(GND8) J4.50(GND14) J4.53 J4.54 J5.4 J5.18 J5.21 J5.23 J5.24 J5.25(SH1) J5.26(SH2) J6.4 J6.18 J6.21 J6.23 J6.24 J6.25(SH1) J6.26(SH2) J7.5 J7.18 J7.19 J7.26 J7.27 J7.34 J7.35 J7.36 J7.41(SH1) J7.42(SH2) J8.8(CHS_GND) J9.3(SH1) J9.4(SH2) J10.3(SH1) J10.4(SH2) J11.3(SH1) J11.4(SH2) J12.6 J12.9 J12.14 J12.20 J12.25 J12.30 J13.1 J14.5(GND) J14.8(SH1) J14.9(SH2) J14.10(SH3) J14.11(SH4) LED1.1(CATHODE) Q1.2(EMITTER) Q3.2(EMITTER) Q4.2(EMITTER) R4.2 R5.2 R7.2 R13.2 R44.2 R46.2 R47.2 R48.2 R60.2 R62.2 R66.2 R68.2 R69.2 R77.2 R83.2 R84.2 R92.2 R93.2 SW1.2(B1) SW2.1(A1) SW2.2(A2) SW3.1(A1) SW3.2(A2) SW4.1(A1) SW4.2(A2) U1.4(GND) U1.8(O\E\) U2.2(GND) U3.1(GND0) U3.11(GND1) U3.24(GND2) U3.27(GND3) U3.30(GND4) U3.39(GND5) U3.42(GND6) U3.45(GND7) U3.48(GND8) U3.51(GND9) U3.54(GND10) U3.57(GND11) U3.60(GND13) U3.61(GND14) U3.62(GND15) U3.63(GND16) U3.64(GND17) U3.67(GND18) U3.69(GND19) U3.71(GND20) U3.74(GND21) U3.77(GND22) U3.85(GND23) U3.88(GND24) U3.90(GND25) U3.92(GND26) U3.95(GND27) U3.98(GND28) U3.101(GND29) U3.110(GND30) U3.118(GND12) U3.120(GND31) U4.5(GND) U4.13(EP) U5.9(GND) U5.25(EPAD) U6.25(VSS) U7.2(GND) U8.2(GND) U9.3(GND1) U9.8(GND2) U10.1(GND1) U10.3(GND2) U12.2 U13.2(GND) U14.2(GND) U15.2(GND) U16.2(GND) U17.7(GND) Y1.2(GND1) Y1.4(GND2) Z1.2 Z2.2
VCC3V3_SD: C10.1 C11.1 J2.4(VDD) R15.2
VCC5V0_SYS: C2.1 C3.1 C4.1 C52.1 C53.1 D3.1 J1.A4(VBUS1) J1.A9(VBUS2) J1.B4(VBUS4) J1.B9(VBUS3) J12.2 J12.4 R6.1 R8.1 R12.1 U2.4(VIN) U3.65(POWER_5V_IN0) U3.66(POWER_5V_IN1) U7.5(IN) U8.5(IN) U13.5(IN) U14.5(IN) U15.5(IN) U17.6(VCC)
VCC_1V8: C12.1 R22.1 R29.1 R31.1 R33.1 R35.1 R79.1 R80.1 R94.2 U3.68(VCC_1V8) U4.12(VCCA)
VCC_3V3: C1.1 C5.1 C6.1 C7.1 C8.1 C9.1 C13.1 C14.1 C19.1 C27.1 C33.1 C34.1 C35.1 C36.1 J4.2(VBAT1) J4.24(VBAT5) J4.39(VBAT2) J4.41(VBAT3) J4.52(VBAT4) J12.1 J12.17 L1.2 Q2.2(SOURCE) R1.1 R9.1 R10.1 R15.1 R26.1 R27.1 R28.1 R30.1 R32.1 R34.1 R36.1 R45.1 R51.1 R64.1 R65.1 R74.1 R75.1 U1.9(VCC) U4.11(VCCB) U5.21(VCC) U16.5(IN)
VCC_3V3_EN: R14.1 U3.70(VCC_3V3)
VCC_WLAN: C28.1 C29.1 Q2.3(DRAIN) U10.6(VDD_3V3)
VDD_CAM0_5V: C37.1 C38.1 J5.1 J5.2 J5.3 U13.1(OUT)
VDD_CAM1_5V: C39.1 C40.1 J6.1 J6.2 J6.3 U14.1(OUT)
VDD_LCD_3V3: C43.1 C44.1 J7.37 J7.38 R63.1 U16.1(OUT)
VDD_LCD_5V: C41.1 C42.1 J7.39 J7.40 U15.1(OUT)
CAM0_NRST: J5.22 U5.2(P0_1)
CAM0_PWDN: J5.15 U5.1(P0_0)
CAM0_PWR_EN: R59.1 U3.59(MIPI_CLK0_OUT   VI_CIF_CLKO_M0   GPIO3_C4_D)
CAM1_NRST: J6.22 U5.4(P0_3)
CAM1_PWDN: J6.15 U5.3(P0_2)
CAM1_PWR_EN: R61.1 U3.58(VI_BT656_D2_M0   VI_BT1120_D10   PWM7_IR_M2   MIPI_CLK1_OUT   VI_CIF_D10   GPIO3_C6_D)
DBG_DN: R3.2 U1.7(D1-)
DBG_DP: R2.2 U1.1(D1+)
DBG_RX: J13.2 R89.1 Z2.1
DBG_TX: J13.3 R88.1 Z1.1
DC_EN: R12.2 R14.2 U2.1(EN)
DISP: J7.7 R63.2
DM1: J3.2(D-) R37.1 U9.2(D1-) U9.9(NC2)
DM2: J3.8(D-) R40.1 U9.5(D2-) U9.6(NC4)
DP1: J3.3(D+) R38.1 U9.1(D1+) U9.10(NC1)
DP2: J3.9(D+) R42.1 U9.4(D2+) U9.7(NC3)
FEPHY_LINK: R78.1 U3.102(VI_BT656_D7_M0   VI_BT1120_D15   PWM1_M2   VI_CIF_D15   GPIO3_D3_D)
FEPHY_RXN: R70.1 U3.25(FEPHY_RXN)
FEPHY_RXP: R71.1 U3.26(FEPHY_RXP)
FEPHY_SPD: R76.1 U3.103(VI_CIF_VSYNC_M0   GPIO3_C5_D)
FEPHY_TXN: R72.1 U3.28(FEPHY_TXN)
FEPHY_TXP: R73.1 U3.29(FEPHY_TXP)
GPIO0_A0: J12.7 U3.111(RTC_CLK_OUT   CLK_32K_IN   REF_CLK_OUT   UART0_RX_M0   GPIO0_A0_Z)
GPIO0_A1: J12.11 U3.112(PWM2_M0   UART0_TX_M0   GPIO0_A1_D)
GPIO0_A2: J12.13 U3.113(PWM3_IR_M0   GPIO0_A2_D)
GPIO0_A4: J12.15 U3.115(PWM1_M0   PWR_CTRL_M0   GPIO0_A4_D)
GPIO0_A5: J12.16 U3.116(I2C1_SCL_M0   PWM5_M0   UART1_RTS_M0   GPIO0_A5_D)
GPIO5_P1_0: J12.18 U5.10(P1_0)
GPIO5_P1_1: J12.22 U5.11(P1_1)
GPIO5_P1_2: J12.26 U5.12(P1_2)
HUB_3V3: C20.1 C21.1 R39.1 R41.1 R43.1 R45.2 U6.1(OVCUR#) U6.20(VDD3V3)
I2C3_SCL_LT: J6.6 J12.5 R23.1 R34.2 U4.8(B3)
I2C3_SCL_M2: R33.2 U3.75(VI_BT656_D5_M0   VI_BT1120_D13   UART5_RTS_M2   I2C3_SCL_M2   VI_CIF_D13   GPIO3_D1_D) U4.3(A3)
I2C3_SDA_LT: J6.5 J12.3 R24.1 R36.2 U4.7(B4)
I2C3_SDA_M2: R35.2 U3.76(VI_BT656_D6_M0   VI_BT1120_D14   UART5_CTS_M2   I2C3_SDA_M2   VI_CIF_D14   GPIO3_D2_D) U4.4(A4)
I2C4_SCL_LT: J5.6 J7.1 J12.28 R30.2 U4.10(B1)
I2C4_SCL_M2: R29.2 U3.72(VI_BT656_D3_M0   VI_BT1120_D11   UART5_TX_M2   I2C4_SCL_M2   VI_CIF_D11   GPIO3_C7_D) U4.1(A1)
I2C4_SDA_LT: J5.5 J7.2 J12.27 R32.2 U4.9(B2)
I2C4_SDA_M2: R31.2 U3.73(VI_BT656_D4_M0   VI_BT1120_D12   UART5_RX_M2   I2C4_SDA_M2   VI_CIF_D12   GPIO3_D0_D) U4.2(A2)
LCD_INT: J7.3 R65.2 U3.6(I2C0_SDA_M0   UART1_RX_M0   GPIO1_A4_D)
LCD_PWM_BL: J7.6 U3.4(VI_CIF_D0_M1   CPU_AVS   PWM0_M0   GPIO1_A2_D)
LCD_RST: J7.4 R64.2 U3.5(I2C0_SCL_M0   UART1_TX_M0   GPIO1_A3_D)
LINEOUT: C54.1 U3.89(CODEC_LINEOUT)
MICIN0_N: C50.2 J9.2 R83.1 U3.96(MICIN0_N)
MICIN0_P: C50.1 J9.1 R81.1 U3.97(MICIN0_P)
MICIN1_N: C51.2 J10.2 R84.1 U3.99(MICIN1_N)
MICIN1_P: C51.1 J10.1 R82.1 U3.100(MICIN1_P)
MIPI_CSI_RX_CLK0N: J5.10 U3.49(VI_BT656_D0_M0   VI_BT1120_D8   LVDS_RX_CLK0N   MIPI_CSI_RX_CLK0N   VI_CIF_D8_M0   GPI3_C0_D)
MIPI_CSI_RX_CLK0P: J5.9 U3.50(VI_BT656_D1_M0   VI_BT1120_D9   LVDS_RX_CLK0P   MIPI_CSI_RX_CLK0P   VI_CIF_D9_M0   GPI3_C1_D)
MIPI_CSI_RX_CLK1N: J6.10 U3.40(VI_BT1120_D2   LVDS_RX_CLK1N   MIPI_CSI_RX_CLK1N   VI_CIF_D2_M0   GPI3_B2_D)
MIPI_CSI_RX_CLK1P: J6.9 U3.41(VI_BT1120_D3   LVDS_RX_CLK1P   MIPI_CSI_RX_CLK1P   VI_CIF_D3_M0   GPI3_B3_D)
MIPI_CSI_RX_D0N: J5.12 U3.55(VI_BT656_CLK_M0   VI_BT1120_CLK   LVDS_RX_D0N   MIPI_CSI_RX_D0N   VI_CIF_CLKI_M0   GPI3_C2_D)
MIPI_CSI_RX_D0P: J5.11 U3.56(LVDS_RX_D0P   MIPI_CSI_RX_D0P   VI_CIF_HREF_M0   GPI3_C3_D)
MIPI_CSI_RX_D1N: J5.8 U3.52(VI_BT1120_D6   LVDS_RX_D1N   MIPI_CSI_RX_D1N   VI_CIF_D6_M0   GPI3_B6_D)
MIPI_CSI_RX_D1P: J5.7 U3.53(VI_BT1120_D7   LVDS_RX_D1P   MIPI_CSI_RX_D1P   VI_CIF_D7_M0   GPI3_B7_D)
MIPI_CSI_RX_D2N: J6.12 U3.46(VI_BT1120_D4   LVDS_RX_D2N   MIPI_CSI_RX_D2N   VI_CIF_D4_M0   GPI3_B4_D)
MIPI_CSI_RX_D2P: J6.11 U3.47(VI_BT1120_D5   LVDS_RX_D2P   MIPI_CSI_RX_D2P   VI_CIF_D5_M0   GPI3_B5_D)
MIPI_CSI_RX_D3N: J6.8 U3.43(VI_BT1120_D0   LVDS_RX_D3N   MIPI_CSI_RX_D3N   VI_CIF_D0_M0   GPI3_B0_D)
MIPI_CSI_RX_D3P: J6.7 U3.44(VI_BT1120_D1   LVDS_RX_D3P   MIPI_CSI_RX_D3P   VI_CIF_D1_M0   GPI3_B1_D)
NPOR: R87.1 U3.119(NPOR)
PWM3_IR_M1: J12.29 U3.7(PWM3_IR_M1   UART4_RX_M0   GPIO1_B0_D)
PWM7_IR_M1: J12.12 U3.8(SPI1_CS1_M0   VI_CIF_D1_M1   PWM7_IR_M1   UART4_TX_M0   GPIO1_B1_D)
RGB_LCD_EN: R67.1 U3.117(I2C1_SDA_M0   PWM6_M0   UART1_CTS_M0   GPIO0_A6_D)
S_SET: R1.2 SW1.1(A1) U1.10(S)
SARADC_IN0_REC: R90.1 U3.87(SARADC_IN0   GPIO4_C0_Z)
SARADC_IN1: R91.1 U3.86(PWM1_M1   SARADC_IN1   GPIO4_C1_Z)
SDMMC_CLK: D7.1 J2.5(CLK) U3.78(JTAG_LPMCU_TCK_M1    I2C0_SCL_M2   PWM10_M0   UART5_RTS_M0   SDMMC_CLK   GPIO3_A4_D)
SDMMC_CMD: R18.1 U3.84(JTAG_LPMCU_TMS_M1   I2C0_SDA_M2   PWM11_IR_M0   UART5_CTS_M0   SDMMC_CMD   GPIO3_A5_U)
SDMMC_D0: R19.1 U3.80(PWM8_M0   UART2_RX_M0   SDMMC_D0   GPIO3_A3_U)
SDMMC_D1: R20.1 U3.81(PWM9_M0   UART2_TX_M0   SDMMC_D1   GPIO3_A2_U)
SDMMC_D2: R16.1 U3.82(JTAG_HPMCU_TCK_M1   JTAG_CPU_TCK_M0   UART5_RX_M0   SDMMC_D2   GPIO3_A7_U)
SDMMC_D3: R17.1 U3.83(JTAG_HPMCU_TMS_M1   JTAG_CPU_TMS_M0   UART5_TX_M0   SDMMC_D3   GPIO3_A6_U)
SDMMC_DET: R21.1 U3.79(SDMMC_DET   GPIO3_A1_U)
SIM_CLK0: J4.12(USIM-CLK) R54.1
SIM_DATA0: J4.10(USIM-DATA) R56.1
SIM_RST0: J4.14(USIM-RST) R55.1
SIM_VDD: J4.8(USIM-VDD) J14.1(VCC) R53.1 U12.1
SPI1_CLK_M0: J12.23 U3.108(SPI1_CLK_M0   I2C2_SCL_M1   UART1_RX_M2   EMMC_D5   GPIO4_A7_U)
SPI1_CS0_M0: J12.24 U3.109(SPI1_CS0_M0   I2C2_SDA_M1   UART1_TX_M2   EMMC_D4   GPIO4_A5_U)
SPI1_MISO_M0: J12.21 U3.106(SPI1_MISO_M0   I2C0_SDA_M1   UART0_RX_M2   EMMC_D7   GPIO4_A0_U)
SPI1_MOSI_M0: J12.19 U3.107(SPI1_MOSI_M0   I2C0_SCL_M1   UART0_TX_M2   EMMC_D6   GPIO4_A1_U)
SPK_CTRL: U5.8(P0_7) U17.1(SDN)
SYS_LED: R11.1 U5.5(P0_4)
UART2_DBG_RX: R89.2 U3.9(JTAG_HPMCU_TMS_M0   JTAG_LPMCU_TMS_M0   JTAG_CPU_TMS_M1   UART2_RX_M1   GPIO1_B3_U)
UART2_DBG_TX: R88.2 U3.10(JTAG_HPMCU_TCK_M0   JTAG_LPMCU_TCK_M0   JTAG_CPU_TCK_M1   UART2_TX_M1   GPIO1_B2_D)
UART3_RX_M0: J12.10 U3.3(I2C2_SDA_M0   PWM4_M0   UART3_RX_M0   GPIO1_A1_D)
UART3_TX_M0: J12.8 U3.2(I2C2_SCL_M0   PWM7_IR_M0   UART3_TX_M0   GPIO1_A0_D)
USB_4G_DM3: R57.2 U6.7(DM3)
USB_4G_DP3: R58.2 U6.8(DP3)
USB_DM1: R37.2 U6.11(DM1)
USB_DM2: R40.2 U6.9(DM2)
USB_DP1: R38.2 U6.12(DP1)
USB_DP2: R42.2 U6.10(DP2)
USB_HOST_EN: R47.1 U5.7(P0_6) U7.4(EN) U8.4(EN)
USB_HUB_DM: U1.6(D2-) U6.14(DMU)
USB_HUB_DP: U1.2(D2+) U6.15(DPU)
USB_RV_DM: U1.5(D-) U3.93(USB_DM)
USB_RV_DP: U1.3(D+) U3.94(USB_DP)
USB_VBUS0: C17.1 C18.1 J3.1(VBUS) U7.1(OUT)
USB_VBUS1: C22.1 C23.1 J3.7(VBUS) U8.1(OUT)
USB_VBUSDET: R6.2 R7.1 U3.91(USB_VBUSDET)
USB_WLAN_DM4: R49.1 U6.5(DM4)
USB_WLAN_DP4: R50.1 U6.6(DP4)
VO_LCDC_CLK: R95.1 U3.12(I2C3_SCL_M1   AUD_DSM_N   UART5_TX_M1   PWM11_IR_M2   VI_CIF_CLKO_M1   VO_LCDC_CLK   GPIO1_D3_D)
VO_LCDC_D0: J7.17 U3.16(VI_BT656_D7_M1   UART4_CTS_M1   PWM11_IR_M1   _ _ _ VI_CIF_D9_M1   VO_LCDC_D0   GPIO1_C7_D)
VO_LCDC_D1: J7.16 U3.17(VI_BT656_D6_M1   UART4_RTS_M1   PWM10_M1   VI_CIF_D8_M1   VO_LCDC_D1   GPIO1_C6_D)
VO_LCDC_D2: J7.15 U3.18(VI_BT656_D5_M1   SDIO_D2_M1   UART4_TX_M1   PWM9_M1   VI_CIF_D7_M1   VO_LCDC_D2   GPIO1_C5_D)
VO_LCDC_D3: J7.14 U3.19(VI_BT656_D4_M1    SDIO_D3_M1   UART4_RX_M1   PWM8_M1   VI_CIF_D6_M1   VO_LCDC_D3   GPIO1_C4_D)
VO_LCDC_D4: J7.13 U3.20(VI_BT656_D3_M1   I2C4_SDA_M1   SDIO_CMD_M1   SPI0_MISO_M0   PWM6_M2   VI_CIF_D5_M1   VO_LCDC_D4   GPIO1_C3_D)
VO_LCDC_D5: J7.12 U3.21(VI_BT656_D2_M1   I2C4_SCL_M1   SDIO_CLK_M1   SPI0_MOSI_M0   PWM5_M2   VI_CIF_D4_M1   VO_LCDC_D5   GPIO1_C2_D)
VO_LCDC_D6: J7.25 U3.22(VI_BT656_D1_M1   SDIO_D0_M1   SPI0_CLK_M0   PWM4_M2   VI_CIF_D3_M1   VO_LCDC_D6   GPIO1_C1_D)
VO_LCDC_D7: J7.24 U3.23(VI_BT656_D0_M1   SDIO_D1_M1   SPI0_CS0_M0   PWM2_M2   VI_CIF_D2_M1   VO_LCDC_D7   GPIO1_C0_D)
VO_LCDC_D8: J7.23 U3.105(I2C4_SDA_M0   UART1_CTS_M1   VO_LCDC_D8   I2S0_SCLK   SDIO_D1_M0   GPIO2_A0_D)
VO_LCDC_D9: J7.22 U3.104(I2C4_SCL_M0   UART1_RTS_M1   VO_LCDC_D9   I2S0_LRCK   SDIO_D0_M0   GPIO2_A1_D)
VO_LCDC_D10: J7.21 U3.38(VO_LCDC_D10   I2S0_MCLK   SDIO_CLK_M0   GPIO2_A2_D)
VO_LCDC_D11: J7.20 U3.37(VO_LCDC_D11   I2S0_SDO3_SDI1   SDIO_CMD_M0   GPIO2_A3_D)
VO_LCDC_D12: J7.33 U3.36(UART1_TX_M1   VO_LCDC_D12   I2S0_SDO0   SDIO_D3_M0   GPIO2_A4_D)
VO_LCDC_D13: J7.32 U3.35(UART1_RX_M1   VO_LCDC_D13   I2S0_SDI0    SDIO_D2_M0   GPIO2_A5_D)
VO_LCDC_D14: J7.31 U3.34(FLASH_TRIGOUT   I2C3_SCL_M0   PWM2_M1   VO_LCDC_D14   I2S0_SDO2_SDI2   UART0_RTS_M1   GPIO2_A6_D)
VO_LCDC_D15: J7.30 U3.33(PRELIGHT_TRIGOUT   I2C3_SDA_M0   PWM4_M1   VO_LCDC_D15   I2S0_SDO1_SDI3   UART0_CTS_M1   GPIO2_A7_D)
VO_LCDC_D16: J7.29 U3.31(PWM5_M1   VO_LCDC_D16   I2C1_SCL_M1   UART0_RX_M1   GPIO2_B0_D)
VO_LCDC_D17: J7.28 U3.32(PWM6_M1   VO_LCDC_D17   I2C1_SDA_M1   UART0_TX_M1   GPIO2_B1_D)
VO_LCDC_DEN: J7.8 U3.15(VI_BT656_CLK_M1   UART3_TX_M1   UART5_RTS_M1   PWM3_IR_M2   VI_CIF_CLKI_M1   VO_LCDC_DEN   GPIO1_D0_D)
VO_LCDC_HSYNC: R96.1 U3.14(UART3_RX_M1   UART5_CTS_M1   PWM10_M2   VI_CIF_HREF_M1   VO_LCDC_HSYNC   GPIO1_D1_D)
VO_LCDC_VSYNC: R97.1 U3.13(SPI0_CS1_M0   I2C3_SDA_M1   AUD_DSM_P   UART5_RX_M1   PWM0_M1   VI_CIF_VSYNC_M1   VO_LCDC_VSYNC   GPIO1_D2_D)
WIFI_PWR_EN: R52.1 U5.6(P0_5)
XL9535_INT: R25.1 U3.114(PWR_CTRL_M1   GPIO0_A3_U)
N19537137: J11.1 U17.8(VO2)
N19537140: J11.2 R86.2 U17.5(VO1)
N19537426: R85.2 R86.1 U17.4(IN-)
N19538834: C55.1 U17.2(BYPASS) U17.3(IN+)
N21425973: J1.A5(CC1) R5.1
N21425975: J1.B5(CC2) R4.1
N21432968: D1.2 J1.A6(DP1) J1.B6(DP2) R2.1
N21432971: D2.2 J1.A7(DN1) J1.B7(DN2) R3.1
N23042290: LED2.2(ANODE) R9.2
N23042305: LED2.1(CATHODE) Q1.3(COLLECTOR)
N23503644: D10.1 J2.1(DAT2) R16.2
N23503648: D9.1 J2.2(CD/DAT3) R17.2
N23503652: D8.1 J2.3(CMD) R18.2
N23503668: D6.1 J2.7(DAT0) R19.2
N23503672: D5.1 J2.8(DAT1) R20.2
N23503676: D4.1 J2.9(CD) R21.2
N23656755: L1.1 U2.3(SW)
N23656759: C5.2 R10.2 R13.1 U2.5(FB)
N23695731: C15.1 U6.3(XOUT) Y1.3
N23695751: C16.2 U6.4(XIN) Y1.1
N23695813: R43.2 U6.18(PSELF)
N23695825: R41.2 U6.16(RESET#/CDP)
N23695839: R39.2 U6.17(NC2)
N23695875: R44.1 U6.13(LED3/SCL)
N23697039: R48.1 U8.3(ISET)
N23697128: R46.1 U7.3(ISET)
N23704623: R67.2 R68.1 U15.4(EN) U16.4(EN)
N23704651: R69.1 U16.3(ISET)
N23704740: R66.1 U15.3(ISET)
N23717309: C47.1 J8.13(SH1) J8.14(SH2) R77.1
N23717611: C46.1 J8.4(CT2)
N23717616: C45.1 J8.5(CT1)
N23717674: J8.1(TD+) R73.2
N23717677: J8.2(TD-) R72.2
N23717680: J8.3(RD+) R71.2
N23717683: J8.6(RD-) R70.2
N23718997: C24.2 C26.1 U10.2(RF_OUT)
N23719030: C27.2 Q2.1(GATE) R51.2 R52.2
N23719056: R50.2 U10.4(DP)
N23719058: R49.2 U10.5(DM)
N23719088: C24.1 C25.1 CN1.1
N23722440: C48.1 R79.2 R81.2
N23723488: C49.1 R80.2 R82.2
N23729410: Q3.1(BASE) R76.2
N23729602: Q4.1(BASE) R78.2
N23729707: J8.9(LED_G_A) R75.2
N23729710: J8.10(LED_G_K) Q4.3(COLLECTOR)
N23729715: J8.11(LED_Y_K) Q3.3(COLLECTOR)
N23729724: J8.12(LED_Y_A) R74.2
N23759751: Q1.1(BASE) R11.2
N23760169: LED1.2(ANODE) R8.2
N23768401: R59.2 R93.1 U13.4(EN)
N23768412: R60.1 U13.3(ISET)
N23768535: R61.2 R92.1 U14.4(EN)
N23768546: R62.1 U14.3(ISET)
N23809669: C30.1 J14.7(I/O) R53.2 R56.2 U12.5
N23809673: C32.1 J14.2(RST) R55.2 U12.6
N23809721: C31.1 J14.3(CLK) R54.2 U12.4
N23809831: J4.38(USB-D+) R58.1
N23809847: J4.36(USB-D-) R57.1
N23819356: D11.2 R87.2 SW2.3(B1) SW2.4(B2)
N23820735: C54.2 R85.1
N23825175: R28.2 U5.24(A2)
N23825177: R27.2 U5.23(A1)
N23825179: R26.2 U5.18(A0)
N23825209: R23.2 U5.19(SCL)
N23825224: R24.2 U5.20(SDA)
N23825226: R25.2 U5.22(\I\N\T\)
N23825314: R22.2 U4.6(OE)
N23848065: D12.2 R90.2 SW3.3(B1) SW3.4(B2)
N23848217: D13.2 R91.2 R94.1 SW4.3(B1) SW4.4(B2)
N23865153: J7.9 R97.2
N23865156: J7.10 R96.2
N23865159: J7.11 R95.2

Pads without a net: J1 A8 B8; J4 1 3 5 6 7 11 13 16 17 19 20 22 23 25 28 30 31 32 33 42 44 45 46 47 48 49 51; J5 13 14 16 17 19 20; J6 13 14 16 17 19 20; J8 7; J14 4 6; U5 13 14 15 16 17; U6 2 19 21 22 23 24; U12 3

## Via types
v1: diameter 0.508, hole 0.254, TOP to BOTTOM, 726 vias

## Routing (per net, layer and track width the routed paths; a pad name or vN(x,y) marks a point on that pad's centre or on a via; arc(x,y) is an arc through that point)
GND: length 579.1
  TOP w0.152: v1(76.94,11.02) 76.61,11.35 76.61,12.7 v1(76.94,13.03)
  TOP w0.203: U3.30 57.22,7.72 v1(57.18,7.67)
  TOP w0.254: v1(30.63,43.56) 30.82,43.76 U3.85 ; v1(60.92,36.54) 60.8,36.65 U3.54 ; C11.2 v1(18.67,46.74) ; D11.1 v1(79.5,28.75) ; U3.98 v1(25.55,35.55) ; U3.1 v1(25.33,11.43) ; C29.2 v1(63.12,38.81) ; SW2.1 v1(82.99,32.08) ; Q1.2 v1(34.46,2.73) ; v1(74.56,45.29) Z1.2 Z2.2 v1(73.52,46.91) ; J7.5 31.52,50.76 31.39,50.88 v1(31.39,51) ; SW3.2 v1(82.99,37.51) ; C46.2 v1(18.87,15.23) ; R84.2 v1(62.37,49.27) ; J7.26 v1(42.02,51.01) ; Q4.2 v1(30.77,2.76) ; U3.57 v1(60.66,39.95) ; U12.2 18.59,36.32 18.77,36.5 18.77,37.39 v1(18.69,37.47) 18.7,37.47 C30.2 ; U3.51 60.66,33.36 v1(60.92,33.61) ; D9.2 v1(18.67,44.2) 18.67,43.97 19.43,43.21 D7.2 ; U3.48 60.59,30.06 60.81,30.28 v1(60.96,30.28) ; U3.60 v1(60.65,43.25) ; v1(39.65,43.28) 39.63,43.31 U3.77 ; C32.2 v1(16.05,33.16) ; SW3.1 v1(82.99,39.54) ; J7.18 v1(38.02,51.02) ; U3.110 v1(25.83,22.36) ; J7.34 v1(46.02,48.75) ; C10.2 v1(21.21,46.74) ; C45.2 v1(18.6,4.83) ; Q3.2 27.09,2.88 v1(27.22,2.76) ; D6.2 v1(18.67,48.01) ; SW4.1 v1(82.99,46.99) ; v1(65.06,20.37) v1(66.06,20.37) v1(67.06,20.37) v1(68.06,20.37) v1(69.06,20.37) v1(70.06,20.37) ; D13.1 v1(79.5,42.67) ; D12.1 v1(79.5,36.12) ; SW4.2 v1(82.99,44.97) ; D8.2 v1(18.67,45.47) ; U3.88 v1(27.52,43.56) ; U17.7 v1(64.26,44.58) ; D5.2 v1(18.67,40.51) ; U3.67 v1(50.62,43.51) ; C28.2 v1(63.12,34.04) ; U3.45 57.74,26.76 v1(57.58,26.59) ; U3.69 v1(48.43,43.51) ; SW2.2 v1(82.99,30.06) ; U3.39 v1(57.15,20.15) ; C53.2 69.46,43.22 v1(69.75,43.51) ; D10.2 v1(16.11,43.17) ; U3.101 v1(25.55,32.25) ; D4.2 v1(18.67,49.15) ; R83.2 v1(72.53,49.28)
  TOP w0.381: v1(69.82,38.89) 69.13,39.59 C52.2
  TOP w0.508: 82.67,7.97 J1.C1 ; J1.C1 83.72,7.22 ; J1.C1 83.72,8.73 ; J2.10 13.99,55 ; J2.10 12.9,54.19 ; J2.10 15.08,54.19 ; 7.7,33.36 J3.12 ; J3.12 9.2,34.86 ; J3.12 6.2,34.86 ; J3.12 7.7,36.36 ; 53.55,52.2 J11.4 ; J11.4 54.8,53.9 ; J11.4 52.29,53.9 ; J3.6 13.5,36.36 ; J3.6 15,34.86 ; J3.6 12,34.86 ; J3.6 13.5,33.36 ; 13.5,23.81 J3.4 ; J3.4 14.5,24.81 ; J3.4 12.5,24.81 ; J3.4 13.5,25.81 ; 82.67,16.61 J1.C2 ; J1.C2 83.72,15.86 ; J1.C2 83.72,17.37 ; 71.46,38.89 H2.1 ; H2.1 73.66,36.68 ; H2.1 73.66,41.09 ; J1.C4 80.84,16.61 ; J1.C4 79.53,17.37 ; J1.C4 79.53,15.86 ; J1.C4 78.23,16.61 ; 12,21.76 J3.5 ; J3.5 15,21.76 ; J3.5 13.5,23.26 ; J3.5 13.5,20.26 ; J12.25 46.09,4.79 ; J12.25 44.08,4.79 ; J12.25 45.09,5.79 ; 77.6,52.2 J9.3 ; J9.3 78.85,53.9 ; J9.3 76.34,53.9 ; J2.12 5.8,38.69 ; J2.12 4.39,39.66 ; J2.12 4.39,37.73 ; J2.12 2.98,38.69 ; J1.C3 79.53,8.73 ; J1.C3 78.23,7.97 ; J1.C3 80.84,7.97 ; J1.C3 79.53,7.22 ; H1.1 73.66,16.91 ; H1.1 73.66,12.5 ; H1.1 71.46,14.71 ; 58.64,53.9 J11.3 59.9,52.2 ; 62.4,52.2 J10.4 63.65,53.9 ; 10.5,23.81 J3.10 ; J3.10 11.5,24.81 ; J3.10 9.5,24.81 ; J3.10 10.5,25.81 ; J2.13 13.99,40.69 ; J2.13 12.9,39.59 ; J2.13 13.99,38.5 ; J2.13 15.08,39.59 ; 69.48,2.25 J12.6 ; J12.6 70.48,3.25 ; J12.6 71.49,2.25 ; J12.6 70.48,1.24 ; 7.7,20.26 J3.11 ; J3.11 6.2,21.76 ; J3.11 9.2,21.76 ; J3.11 7.7,23.26 ; J13.1 72.58,43.77 ; J13.1 71.63,44.72 ; J13.1 71.63,42.82 ; J2.11 5.8,54.19 ; J2.11 2.98,54.19 ; J2.11 4.39,53.23 ; J2.11 4.39,55.16 ; J7.41 50.67,53.9 ; J7.41 51.87,52.2 ; J7.41 50.67,50.5 ; 15.39,5.34 J8.8 17.4,5.34 ; J12.9 65.41,5.79 ; J12.9 64.4,4.79 ; J12.9 65.41,3.78 ; J12.9 66.41,4.79 ; J7.42 29.07,52.2 ; J7.42 27.87,53.9 ; J7.42 27.87,50.5 ; 72.5,53.9 J9.4 71.25,52.2 ; J12.14 61.48,2.25 ; U10.3 v1(66.01,23.29) ; 68.75,52.2 J10.3 67.49,53.9
  GND02 w0.508: J3.10 11.5,24.81 ; J3.10 10.5,23.81 ; J3.10 9.5,24.81 ; J3.10 10.5,25.81 ; 78.23,7.97 J1.C3 ; J1.C3 79.53,7.22 ; J1.C3 80.84,7.97 ; J1.C3 79.53,8.73 ; 44.08,4.79 J12.25 ; J12.25 45.09,3.78 ; J12.25 46.09,4.79 ; 12.5,24.81 J3.4 ; J3.4 13.5,25.81 ; J3.4 14.5,24.81 ; J3.4 13.5,23.81 ; 79.53,15.86 J1.C4 ; J1.C4 80.84,16.61 ; J1.C4 78.23,16.61 ; J1.C4 79.53,17.37 ; J3.6 15,34.86 ; J3.6 12,34.86 ; J3.6 13.5,33.36 ; J3.12 9.2,34.86 ; J3.12 6.2,34.86 ; J3.12 7.7,33.36 ; 82.67,7.97 J1.C1 ; J1.C1 83.72,7.22 ; J1.C1 83.72,8.73 ; J13.1 72.58,43.77 ; J13.1 71.63,44.72 ; J13.1 70.67,43.77 ; 41.01,2.25 J12.30 40.01,3.25 ; 52.7,1.24 J12.20 52.7,3.25 ; 16.39,4.54 J8.8 ; J8.8 17.4,5.34 ; J8.8 16.39,6.14 ; J8.8 15.39,5.34 ; 82.67,16.61 J1.C2 ; J1.C2 83.72,17.37 ; J1.C2 83.72,15.86
  PWR03 w0.508: 59.32,2.25 J12.14 ; J12.14 60.33,1.24 ; J12.14 60.33,3.25 ; J12.14 61.33,2.25 ; 71.46,14.71 H1.1 ; H1.1 75.86,14.71 ; H1.1 73.66,12.5 ; H1.1 73.66,16.91 ; J12.6 70.48,3.25 ; J12.6 71.49,2.25 ; J12.6 69.48,2.25 ; J12.6 70.48,1.24 ; J1.C4 80.84,16.61 ; J1.C4 79.53,15.86 ; J1.C4 78.23,16.61 ; J1.C4 79.53,17.37 ; J3.10 11.5,24.81 ; J3.10 10.5,23.81 ; J3.10 10.5,25.81 ; J3.10 9.5,24.81 ; 6.2,21.76 J3.11 ; J3.11 7.7,23.26 ; J3.11 7.7,20.26 ; J3.11 9.2,21.76 ; J8.8 17.4,5.34 ; J8.8 15.39,5.34 ; J8.8 16.39,4.54 ; J8.8 16.39,6.14 ; J12.25 45.09,5.79 ; J12.25 44.08,4.79 ; J12.25 46.09,4.79 ; J12.25 45.09,3.78 ; 73.66,36.68 H2.1 ; H2.1 73.66,41.09 ; H2.1 71.46,38.89 ; H2.1 75.86,38.89 ; 13.5,20.26 J3.5 ; J3.5 12,21.76 ; J3.5 15,21.76 ; J3.5 13.5,23.26 ; J13.1 71.63,44.72 ; J13.1 71.63,42.82 ; J13.1 70.67,43.77 ; J13.1 72.58,43.77 ; 78.23,7.97 J1.C3 ; J1.C3 79.53,8.73 ; J1.C3 80.84,7.97 ; J1.C3 79.53,7.22 ; J3.4 13.5,25.81 ; J3.4 14.5,24.81 ; J3.4 12.5,24.81 ; J3.4 13.5,23.81 ; J3.6 15,34.86 ; J3.6 13.5,33.36 ; J3.6 13.5,36.36 ; J3.6 12,34.86 ; 82.67,16.61 J1.C2 ; J1.C2 83.72,15.86 ; J1.C2 83.72,17.37 ; J12.9 66.41,4.79 ; J12.9 64.4,4.79 ; J12.9 65.41,5.79 ; J12.9 65.41,3.78 ; J12.30 40.01,3.25 ; J12.30 39,2.25 ; J12.30 40.01,1.24 ; J12.30 41.01,2.25 ; 82.67,7.97 J1.C1 ; J1.C1 83.72,8.73 ; J1.C1 83.72,7.22 ; J3.12 9.2,34.86 ; J3.12 6.2,34.86 ; J3.12 7.7,36.36 ; J3.12 7.7,33.36 ; 52.7,1.24 J12.20 ; J12.20 52.7,3.25 ; J12.20 51.7,2.25 ; J12.20 53.71,2.25
  BOTTOM w0.203: U4.13 U4.5 46.71,30.35 v1(46.99,30.07) ; v1(50.81,7.68) 50.28,7.15 48.34,7.15 v1(47.81,7.68) ; U1.4 v1(38.25,30.23) ; v1(46.96,20.57) U5.9 46.96,23.14 v1(46.71,23.39) ; J6.21 31.77,50.62 v1(31.39,51) ; 24.35,6.19 47.1,6.19 47.41,5.88 50.8,5.88 51.34,6.42 53.31,6.42 54.03,7.14 54.03,7.65 v1(54.05,7.67) 54.05,8.59 53.57,9.07 52.14,9.07 50.81,7.74 ; J5.21 v1(49.97,48.36) ; J5.23 v1(48.97,48.36)
  BOTTOM w0.254: 37.11,15.6 36.02,15.6 36.02,16.56 ; 37.11,15.6 38.99,15.6 ; 37.11,15.6 37.1,15.6 Y1.4 36.03,16.55 36.02,16.56 ; C55.2 68.06,39.11 67.82,38.86 ; v1(31.23,33.81) 33.94,33.81 v1(34.22,34.1) 34.76,33.56 34.76,31.66 v1(34.22,31.13) 33.94,31.41 v1(31.23,31.41) ; C35.2 33.49,35.52 v1(33.53,35.48) ; R69.2 v1(78.27,51.01) ; 39.4,18.83 Y1.2 40.35,18.05 v1(40.49,18.19) ; U16.2 v1(75.16,53.92) ; v1(47.97,48.36) 48.47,48.86 J5.24 ; R44.2 v1(35.56,28.31) ; v1(40.49,18.19) v1(40.49,19.46) C15.2 ; v1(40.49,18.19) 41.55,18.19 C20.2 ; v1(40.49,18.19) v1(40.49,16.92) v1(40.49,15.6) 38.99,15.6 ; C12.2 v1(47.72,33.12) ; D2.1 v1(82.55,10.03) ; 38.99,15.6 v1(38.96,15.62) ; U8.2 v1(2.77,25.93) ; J5.18 v1(51.47,48.36) ; J6.18 v1(33.27,51) ; 46.62,46.61 v1(45.3,46.61) ; 36.02,16.56 v1(36.02,18.19) v1(36.02,19.46) C16.1 ; v1(42.42,24.97) 41.99,25.39 C21.2 ; v1(2.92,30.25) 2.77,30.1 U7.2 ; J14.5 15.92,47.84 v1(16.13,48.06) ; v1(67.11,53.92) 67.54,53.49 U15.2 ; v1(40.59,48.36) 40.27,48.68 J6.4 40.28,49.44 ; D1.1 v1(82.55,14.61) ; v1(60.96,30.28) 60.96,30.35 61.65,31.04 61.65,32.88 v1(60.92,33.61) 61.45,34.15 61.45,35.81 60.92,36.34 v1(60.92,36.54) ; R4.2 v1(81.53,14.61) ; R5.2 v1(81.53,10.03) ; R47.2 v1(4.11,22.35) ; v1(32.64,39.22) 32.64,38.98 C34.2 ; C1.2 36.58,33.57 v1(36.78,33.38) 37.51,32.65 U1.8 ; C19.2 v1(41.04,20.46) ; J5.4 v1(58.47,50.72) ; C14.2 v1(46.48,29.08) ; 50.81,7.74 v1(50.81,7.68) ; R48.2 v1(4.11,23.37) ; C13.2 v1(45.58,34.8)
  BOTTOM w0.381: v1(20.12,29.61) 20.32,29.41 J4.29 ; v1(31.45,38) 31.26,37.81 J4.50 ; J4.40 v1(31.23,33.81) ; J4.27 v1(20.12,28.61) ; J4.26 31.1,28.21 v1(31.14,28.17) ; J4.18 v1(31.23,25.01) ; J4.9 20.12,18.21 ; J4.34 v1(31.23,31.41) ; C33.2 v1(33.14,28.17)
  BOTTOM w0.508: 71.63,42.82 J13.1 ; J13.1 70.67,43.77 ; J13.1 71.63,44.72 ; J13.1 72.58,43.77 ; J12.6 70.48,3.25 ; J12.6 71.49,2.25 ; J12.6 70.48,1.24 ; J12.6 69.48,2.25 ; 23.79,41.46 J4.53 20.48,41.46 ; J6.26 44.48,52.15 ; J6.26 43.47,50.95 ; J6.26 42.47,52.15 ; J6.26 43.47,53.35 ; J3.12 9.2,34.86 ; J3.12 7.7,33.36 ; J3.12 7.7,36.36 ; J4.54 22.15,13.44 ; J4.54 20.64,12.16 ; J4.54 23.65,12.16 ; H2.1 73.66,41.69 ; H2.1 73.66,36.08 ; H2.1 70.86,38.89 ; H2.1 76.46,38.89 ; 83.72,7.22 J1.C1 ; J1.C1 83.72,8.73 ; J1.C1 82.67,7.97 ; 12,21.76 J3.5 ; J3.5 13.5,23.26 ; J3.5 15,21.76 ; J1.C3 79.53,8.73 ; J1.C3 79.53,7.22 ; J1.C3 80.84,7.97 ; J1.C3 78.23,7.97 ; 82.67,16.61 J1.C2 ; J1.C2 83.72,17.37 ; J1.C2 83.72,15.86 ; J14.10 2.81,39.82 ; J14.10 1.56,39.12 ; J14.10 1.56,40.53 ; 12,34.86 J3.6 ; J3.6 15,34.86 ; J3.6 13.5,36.36 ; J3.6 13.5,33.36 ; 15.39,5.34 J8.8 ; J8.8 16.39,4.54 ; J8.8 16.39,6.14 ; J8.8 17.4,5.34 ; 6.2,21.76 J3.11 ; J3.11 9.2,21.76 ; J3.11 7.7,23.26 ; J14.8 13.56,40.53 ; J14.8 14.81,39.82 ; J14.8 13.56,39.12 ; J3.10 11.5,24.81 ; J3.10 10.5,25.81 ; J3.10 9.5,24.81 ; J3.10 10.5,23.81 ; 61.67,50.95 J5.26 ; J5.26 60.67,52.15 ; J5.26 62.68,52.15 ; J14.11 2.81,52.82 ; J14.11 1.56,53.53 ; J14.11 1.56,52.12 ; H1.1 73.66,17.51 ; H1.1 70.86,14.71 ; H1.1 73.66,11.9 ; H1.1 76.46,14.71 ; 53.71,2.25 J12.20 52.7,1.24 ; 29.74,52.15 J6.25 28.57,50.8 ; 45.09,5.79 J12.25 44.08,4.79 ; 13.5,23.81 J3.4 ; J3.4 12.5,24.81 ; J3.4 13.5,25.81 ; J12.14 61.33,2.25 ; J12.14 60.33,3.25 ; J12.14 59.32,2.25 ; 13.56,52.12 J14.9 ; J14.9 12.31,52.82 ; J14.9 13.56,53.53 ; J14.9 14.81,52.82 ; 78.23,16.61 J1.C4 ; J1.C4 79.53,15.86 ; J1.C4 80.84,16.61 ; J1.C4 79.53,17.37
  BOTTOM w0.762: J5.25 46.77,53.66
  vias: v1(0.81,50.46) v1(0.81,46.65) v1(0.81,42.84) v1(0.81,35.22) v1(0.81,31.41) v1(0.81,27.6) v1(0.81,21.98) v1(0.81,20.98) v1(0.81,19.98) v1(1.21,54.25) v1(2.77,27.93) v1(2.77,26.93) v1(2.92,32.25) v1(2.92,31.25) v1(4.39,30.25) v1(5.42,32.25) v1(6.42,32.25) v1(6.44,27.96) v1(7.44,27.96) v1(7.44,26.96) v1(7.44,25.96) v1(7.47,53.14) v1(7.8,43.15) v1(7.8,41.88) v1(7.8,40.61) v1(7.8,39.34) v1(8.59,31.7) v1(8.71,55.19) v1(8.74,53.14) v1(10.01,53.14) v1(10.13,42.75) v1(10.79,45.03) v1(11.28,53.14) v1(12.34,12.12) v1(12.34,10.85) v1(12.34,9.58) v1(12.34,8.31) v1(12.34,7.04) v1(12.4,16.46) v1(12.52,55.19) v1(12.55,40.84) v1(13.06,50.8) v1(13.08,48.77) v1(13.16,2.08) v1(13.16,0.81) v1(13.39,19.3) v1(14.43,0.81) v1(14.66,19.3) v1(14.99,29.39) v1(15.65,27.48) v1(15.62,25.78) v1(15.93,19.3) v1(16.11,40.22) v1(16.11,39.22) v1(16.05,34.43) v1(16.19,54.16) v1(16.33,15.23) v1(16.48,28.3) v1(16.56,51.18) v1(17.6,15.23) v1(18.03,30.94) v1(18.03,28.32) v1(18.06,25.17) v1(18.24,0.81) v1(18.44,19.28) v1(18.44,18.01) v1(18.69,13.61) v1(18.69,12.34) v1(18.67,8) v1(19.66,6.6) v1(20.02,25.15) v1(20.14,34.34) v1(20.12,31.81) v1(20.19,7.98) v1(20.5,51.1) v1(21.21,5.64) v1(22.05,0.81) v1(23.24,10.19) v1(23.42,8) v1(24.24,10.19) v1(25.3,12.95) v1(25.83,20.73) v1(25.83,19.63) v1(25.78,5.66) v1(25.86,0.81) v1(26.62,18.47) v1(26.82,55.19) v1(27.51,12.43) v1(27.58,26.96) v1(27.58,25.96) v1(27.64,14.17) v1(27.71,17.4) v1(28.7,50.32) v1(28.8,23.02) v1(28.8,22.02) v1(29.74,52.68) v1(29.74,51.68) v1(29.67,0.81) v1(30.63,55.19) v1(31.19,30.19) v1(31.19,29.19) v1(31.48,1.58) v1(33.14,13.18) v1(33.17,26.62) v1(33.17,25.62) v1(33.48,0.81) v1(33.66,23.7) v1(34.27,51) v1(34.29,20.4) v1(35.14,14.18) v1(35.48,25.48) v1(35.81,48.21) v1(36.26,21.4) v1(36.5,29.54) v1(37.16,34.95) v1(37.29,0.81) v1(37.39,14.17) v1(37.77,43.33) v1(37.85,36.09) v1(37.79,23.91) v1(37.79,22.91) v1(38.54,46.62) v1(38.79,23.91) v1(38.79,22.91) v1(38.96,14.17) v1(39.21,47.89) v1(39.32,41.78) v1(39.8,35.26) v1(40.51,42.42) v1(41.78,7.47) v1(42.02,52.01) v1(43.05,7.47) v1(43.33,46.63) v1(44.3,46.61) v1(44.32,40.59) v1(44.32,7.47) v1(44.5,39.01) v1(44.65,52.98) v1(45.59,7.47) v1(45.71,24.39) v1(45.71,23.39) v1(45.71,22.39) v1(46.2,43.05) v1(46.71,24.39) v1(46.71,22.39) v1(46.88,31.79) v1(46.97,48.36) v1(47.09,40.59) v1(47.71,24.39) v1(47.71,23.39) v1(47.71,22.39) v1(49.53,26.17) v1(49.53,25.17) v1(50.16,54.23) v1(50.65,35) v1(50.72,36.83) v1(51.59,30.66) v1(51.64,26.09) v1(51.64,24.82) v1(51.64,22.17) v1(51.64,21.13) v1(52.1,51.16) v1(53.37,51.16) v1(53.92,48.31) v1(54.05,47.04) v1(54.64,51.16) v1(55.55,37.13) v1(55.52,34.47) v1(55.5,31.17) v1(55.73,43.18) v1(55.68,29.84) v1(55.83,55.17) v1(55.91,23.77) v1(56.04,26.94) v1(56.08,32.94) v1(56.15,20.15) v1(56.41,47.14) v1(56.79,31.57) v1(57.02,43.17) v1(57.3,55.19) v1(57.3,30.35) v1(57.4,47.96) v1(60.17,51.56) v1(60.83,14.5) v1(60.96,28.73) v1(61.37,50.27) v1(61.37,49.27) v1(61.47,37.67) v1(61.75,13.64) v1(61.93,20.37) v1(62.03,30.76) v1(62.26,44.58) v1(62.37,50.27) v1(62.92,27.79) v1(62.92,9.98) v1(62.92,8.98) v1(62.92,7.98) v1(63.12,33.04) v1(63.26,44.58) v1(63.27,6.92) v1(63.37,50.27) v1(63.37,49.27) v1(64.11,53.92) v1(64.12,34.04) v1(64.12,33.04) v1(64.06,20.37) v1(64.26,42.95) v1(64.27,6.92) v1(64.85,38.91) v1(65.11,53.92) v1(65.12,34.04) v1(65.12,33.04) v1(65.27,6.92) v1(65.66,29.02) v1(65.66,26.02) v1(66.04,11.73) v1(66.11,53.92) v1(66.19,42.42) v1(66.22,38.89) v1(66.27,6.92) v1(66.84,11.73) v1(67.27,6.92) v1(67.54,35.76) v1(68.27,6.92) v1(69.24,47.83) v1(69.19,33.93) v1(69.19,32.93) v1(69.19,31.93) v1(69.53,50.28) v1(69.6,23.75) v1(69.6,22.48) v1(69.9,28.35) v1(70.31,9.04) v1(70.36,11.48) v1(70.53,50.28) v1(70.52,46.91) v1(70.57,17.04) v1(70.57,16.04) v1(70.81,12.27) v1(70.93,30) v1(71.15,23.72) v1(71.15,22.45) v1(71.17,28.35) v1(71.17,27.08) v1(71.53,50.28) v1(71.52,46.91) v1(71.81,11.76) v1(72.03,10.82) v1(72.52,46.91) v1(73.09,10.82) v1(73.16,54.92) v1(73.16,53.92) v1(73.2,9.5) v1(73.53,49.28) v1(74,26.77) v1(74,25.77) v1(74,23.77) v1(74,22.77) v1(74,20.77) v1(74,19.77) v1(74.09,10.82) v1(74.16,54.92) v1(74.16,53.92) v1(74.78,31.95) v1(75.16,54.92) v1(75.27,26.77) v1(75.27,25.77) v1(75.27,21.77) v1(75.27,20.77) v1(75.27,19.77) v1(75.56,45.29) v1(76.05,31.95) v1(76.27,26.77) v1(76.27,25.77) v1(76.27,21.77) v1(76.27,20.77) v1(76.27,19.77) v1(77.32,31.95) v1(77.27,26.77) v1(77.27,25.77) v1(77.27,21.77) v1(77.27,20.77) v1(77.27,19.77) v1(77.37,45.26) v1(77.81,17.71) v1(77.81,16.71) v1(78.03,40.59) v1(78.03,39.32) v1(78.03,38.05) v1(78.03,36.78) v1(78.27,26.77) v1(78.27,23.77) v1(78.27,22.77) v1(78.27,21.77) v1(78.27,20.77) v1(78.27,19.77) v1(78.59,31.95) v1(78.79,46.94) v1(79.2,0.81) v1(79.27,26.77) v1(79.27,25.77) v1(79.27,23.77) v1(79.27,22.77) v1(79.27,21.77) v1(79.27,20.77) v1(79.27,19.77) v1(80.16,55.19) v1(80.27,26.77) v1(80.27,25.77) v1(80.27,19.77) v1(81.53,17.6) v1(81.53,16.6) v1(81.53,15.6) v1(81.53,9.03) v1(81.53,8.03) v1(81.53,7.03) v1(81.79,48.64) v1(82.27,26.77) v1(82.27,19.77) v1(83.27,26.77) v1(83.27,25.77) v1(83.27,24.77) v1(83.27,19.77) v1(83.55,14.61) v1(83.55,10.03) v1(84.19,50.4) v1(84.19,46.59) v1(84.19,42.78) v1(84.19,38.97) v1(84.19,35.16) v1(84.19,31.35) v1(84.19,27.54) v1(84.19,23.73) v1(84.19,13.57) v1(84.19,11.03)
